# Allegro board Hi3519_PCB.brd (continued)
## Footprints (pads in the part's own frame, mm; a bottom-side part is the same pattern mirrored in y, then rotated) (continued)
CAPC2-138-335
  rect 2.032x2.032 hole 1.016: 1(0,0)
  round 2.032 hole 1.016: 2(3.5,0)
CONN80-0_8MM-ERF8-DV
  round 1.524 hole 1.524 unplated: (-17.4,-1.5) (17.4,-1.5)
  rect 0.508x1.27 smd: 1(15.6,2.2) 2(15.6,-2.2) 3(14.8,2.2) 4(14.8,-2.2) 5(14,2.2) 6(14,-2.2) 7(13.2,2.2) 8(13.2,-2.2) 9(12.4,2.2) 10(12.4,-2.2) 11(11.6,2.2) 12(11.6,-2.2) 13(10.8,2.2) 14(10.8,-2.2) 15(10,2.2) 16(10,-2.2) 17(9.2,2.2) 18(9.2,-2.2) 19(8.4,2.2) 20(8.4,-2.2) 21(7.6,2.2) 22(7.6,-2.2) 23(6.8,2.2) 24(6.8,-2.2) 25(6,2.2) 26(6,-2.2) 27(5.2,2.2) 28(5.2,-2.2) 29(4.4,2.2) 30(4.4,-2.2) 31(3.6,2.2) 32(3.6,-2.2) 33(2.8,2.2) 34(2.8,-2.2) 35(2,2.2) 36(2,-2.2) 37(1.2,2.2) 38(1.2,-2.2) 39(0.4,2.2) 40(0.4,-2.2) 41(-0.4,2.2) 42(-0.4,-2.2) 43(-1.2,2.2) 44(-1.2,-2.2) 45(-2,2.2) 46(-2,-2.2) 47(-2.8,2.2) 48(-2.8,-2.2) 49(-3.6,2.2) 50(-3.6,-2.2) 51(-4.4,2.2) 52(-4.4,-2.2) 53(-5.2,2.2) 54(-5.2,-2.2) 55(-6,2.2) 56(-6,-2.2) 57(-6.8,2.2) 58(-6.8,-2.2) 59(-7.6,2.2) 60(-7.6,-2.2) 61(-8.4,2.2) 62(-8.4,-2.2) 63(-9.2,2.2) 64(-9.2,-2.2) 65(-10,2.2) 66(-10,-2.2) 67(-10.8,2.2) 68(-10.8,-2.2) 69(-11.6,2.2) 70(-11.6,-2.2) 71(-12.4,2.2) 72(-12.4,-2.2) 73(-13.2,2.2) 74(-13.2,-2.2) 75(-14,2.2) 76(-14,-2.2) 77(-14.8,2.2) 78(-14.8,-2.2) 79(-15.6,2.2) 80(-15.6,-2.2)
CONN80-0_8MM-ERM8-DV
  round 1.524 hole 1.524 unplated: (-17.4,1.5) (17.4,1.5)
  rect 0.508x1.27 smd: 1(15.6,-1.9) 2(15.6,1.9) 3(14.8,-1.9) 4(14.8,1.9) 5(14,-1.9) 6(14,1.9) 7(13.2,-1.9) 8(13.2,1.9) 9(12.4,-1.9) 10(12.4,1.9) 11(11.6,-1.9) 12(11.6,1.9) 13(10.8,-1.9) 14(10.8,1.9) 15(10,-1.9) 16(10,1.9) 17(9.2,-1.9) 18(9.2,1.9) 19(8.4,-1.9) 20(8.4,1.9) 21(7.6,-1.9) 22(7.6,1.9) 23(6.8,-1.9) 24(6.8,1.9) 25(6,-1.9) 26(6,1.9) 27(5.2,-1.9) 28(5.2,1.9) 29(4.4,-1.9) 30(4.4,1.9) 31(3.6,-1.9) 32(3.6,1.9) 33(2.8,-1.9) 34(2.8,1.9) 35(2,-1.9) 36(2,1.9) 37(1.2,-1.9) 38(1.2,1.9) 39(0.4,-1.9) 40(0.4,1.9) 41(-0.4,-1.9) 42(-0.4,1.9) 43(-1.2,-1.9) 44(-1.2,1.9) 45(-2,-1.9) 46(-2,1.9) 47(-2.8,-1.9) 48(-2.8,1.9) 49(-3.6,-1.9) 50(-3.6,1.9) 51(-4.4,-1.9) 52(-4.4,1.9) 53(-5.2,-1.9) 54(-5.2,1.9) 55(-6,-1.9) 56(-6,1.9) 57(-6.8,-1.9) 58(-6.8,1.9) 59(-7.6,-1.9) 60(-7.6,1.9) 61(-8.4,-1.9) 62(-8.4,1.9) 63(-9.2,-1.9) 64(-9.2,1.9) 65(-10,-1.9) 66(-10,1.9) 67(-10.8,-1.9) 68(-10.8,1.9) 69(-11.6,-1.9) 70(-11.6,1.9) 71(-12.4,-1.9) 72(-12.4,1.9) 73(-13.2,-1.9) 74(-13.2,1.9) 75(-14,-1.9) 76(-14,1.9) 77(-14.8,-1.9) 78(-14.8,1.9) 79(-15.6,-1.9) 80(-15.6,1.9)
DFN2510P10E_AZ1045
  oval 0.254x0.813 smd: 1(-1,-0.525) 5(1,-0.525) 6(1,0.525) 10(-1,0.525)
  oval 0.229x0.813 smd: 2(-0.5,-0.525) 4(0.5,-0.525) 7(0.5,0.525) 9(-0.5,0.525)
  oval 0.356x0.813 smd: 3(0,-0.525) 8(0,0.525)
HEAD0101-T-B
  round 1.778 hole 1.016: 1(0,0)
HSC0402
  rect 0.508x0.508 smd: 1(-0.406,0) 2(0.406,0)
HSC0402-TA
  rect 0.432x0.508 smd: 1(-0.368,0) 2(0.368,0)
HSL1008
  rect 0.94x1.905 smd: 1(-1.029,0) 2(1.029,0)
HSOD323A
  rect 1.118x0.508 smd: 1(1.372,0) 2(-1.372,0)
HSOD882
  rect 0.406x0.483 smd: 1(-0.325,0) 2(0.325,0)
HSR0402-TA
  rect 0.432x0.508 smd: 1(-0.368,0) 2(0.368,0)
HSX2-0302
  rect 1.016x1.778 smd: 1(-1.25,0) 2(1.25,0)
HSX4-0302
  rect 1.397x1.219 smd: 1(-1.1,-0.8) 2(1.1,-0.8) 3(1.1,0.8) 4(-1.1,0.8)
HSX4-0503
  rect 1.524x1.219 smd: 1(-1.27,-1.1) 2(1.27,-1.1) 3(1.27,1.1) 4(-1.27,1.1)
J6-W2_54MM-141R
  rect 1.524x1.905 hole 0.965: 1(-6.35,-2.54)
  oval 1.524x1.905 hole 0.965: 2(-6.35,2.54) 3(-3.81,-2.54) 4(-3.81,2.54) 5(-1.27,-2.54) 6(-1.27,2.54) 7(1.27,-2.54) 8(1.27,2.54) 9(3.81,-2.54) 10(3.81,2.54) 11(6.35,-2.54) 12(6.35,2.54)
MJ8-SRLFY
  round 3.429 hole 3.429 unplated: (-2.794,2.54) (9.906,2.54)
  round 1.27 hole 0.914: 1(0,0) 2(1.016,-1.778) 3(2.032,0) 4(3.048,-1.778) 5(4.064,0) 6(5.08,-1.778) 7(6.096,0) 8(7.112,-1.778) 13(-3.302,-6.604) 14(-1.016,-6.604) 15(8.128,-6.604) 16(10.414,-6.604)
  round 2.159 hole 1.651: 11(-4.508,-0.889) 12(11.62,-0.889)
MLF6-065-0202L
  rect 0.305x0.457 smd: 1(-0.65,-0.925) 2(0,-0.925) 3(0.65,-0.925) 4(0.65,0.925) 5(0,0.925) 6(-0.65,0.925)
  rect 1.524x0.762 smd: 7(0,0)
MLF8M-050-0202L
  rect 0.254x0.559 smd: 1(-0.75,-0.623)
  rect 0.254x0.508 smd: 2(-0.25,-0.648) 3(0.25,-0.648) 4(0.75,-0.648) 5(0.75,0.648) 6(0.25,0.648) 7(-0.25,0.648) 8(-0.75,0.648)
MLF48A-040-0606L
  rect 0.203x0.61 smd: 1(-2.2,-2.879) 2(-1.8,-2.879) 3(-1.4,-2.879) 4(-1,-2.879) 5(-0.6,-2.879) 6(-0.2,-2.879) 7(0.2,-2.879) 8(0.6,-2.879) 9(1,-2.879) 10(1.4,-2.879) 11(1.8,-2.879) 12(2.2,-2.879) 25(2.2,2.879) 26(1.8,2.879) 27(1.4,2.879) 28(1,2.879) 29(0.6,2.879) 30(0.2,2.879) 31(-0.2,2.879) 32(-0.6,2.879) 33(-1,2.879) 34(-1.4,2.879) 35(-1.8,2.879) 36(-2.2,2.879)
  rect 0.61x0.203 smd: 13(2.879,-2.2) 14(2.879,-1.8) 15(2.879,-1.4) 16(2.879,-1) 17(2.879,-0.6) 18(2.879,-0.2) 19(2.879,0.2) 20(2.879,0.6) 21(2.879,1) 22(2.879,1.4) 23(2.879,1.8) 24(2.879,2.2) 37(-2.879,2.2) 38(-2.879,1.8) 39(-2.879,1.4) 40(-2.879,1) 41(-2.879,0.6) 42(-2.879,0.2) 43(-2.879,-0.2) 44(-2.879,-0.6) 45(-2.879,-1) 46(-2.879,-1.4) 47(-2.879,-1.8) 48(-2.879,-2.2)
  rect 4.445x4.445 smd: 49(0,0)
MLF56-050-1105
  rect 0.254x0.61 smd: 1(-4.75,-2.399) 2(-4.25,-2.399) 3(-3.75,-2.399) 4(-3.25,-2.399) 5(-2.75,-2.399) 6(-2.25,-2.399) 7(-1.75,-2.399) 8(-1.25,-2.399) 9(-0.75,-2.399) 10(-0.25,-2.399) 11(0.25,-2.399) 12(0.75,-2.399) 13(1.25,-2.399) 14(1.75,-2.399) 15(2.25,-2.399) 16(2.75,-2.399) 17(3.25,-2.399) 18(3.75,-2.399) 19(4.25,-2.399) 20(4.75,-2.399) 29(4.75,2.399) 30(4.25,2.399) 31(3.75,2.399) 32(3.25,2.399) 33(2.75,2.399) 34(2.25,2.399) 35(1.75,2.399) 36(1.25,2.399) 37(0.75,2.399) 38(0.25,2.399) 39(-0.25,2.399) 40(-0.75,2.399) 41(-1.25,2.399) 42(-1.75,2.399) 43(-2.25,2.399) 44(-2.75,2.399) 45(-3.25,2.399) 46(-3.75,2.399) 47(-4.25,2.399) 48(-4.75,2.399)
  rect 0.61x0.254 smd: 21(5.399,-1.75) 22(5.399,-1.25) 23(5.399,-0.75) 24(5.399,-0.25) 25(5.399,0.25) 26(5.399,0.75) 27(5.399,1.25) 28(5.399,1.75) 49(-5.399,1.75) 50(-5.399,1.25) 51(-5.399,0.75) 52(-5.399,0.25) 53(-5.399,-0.25) 54(-5.399,-0.75) 55(-5.399,-1.25) 56(-5.399,-1.75)
  rect 8.509x2.489 smd: 57(0,0)
MOLEX_47151
  round 1.219 hole 1.219 unplated: (-2.5,2.096) (2.5,2.096)
  oval 0.254x2.667 smd: 1(4.5,4.508) 2(4,4.508) 3(3.5,4.508) 4(3,4.508) 5(2.5,4.508) 6(2,4.508) 7(1.5,4.508) 8(1,4.508) 9(0.5,4.508) 10(0,4.508) 11(-0.5,4.508) 12(-1,4.508) 13(-1.5,4.508) 14(-2,4.508) 15(-2.5,4.508) 16(-3,4.508) 17(-3.5,4.508) 18(-4,4.508) 19(-4.5,4.508)
  oval 1.524x3.302 hole 0.711x2.718: 20(-7.25,3.746) 21(7.25,3.746)
  oval 1.524x2.718 hole 0.711x1.702: 22(-7.25,-2.214) 23(7.25,-2.214)
MSOP8A-26-118
  rect 0.356x1.524 smd: 1(-0.975,-2.2) 2(-0.325,-2.2) 3(0.325,-2.2) 4(0.975,-2.2) 5(0.975,2.2) 6(0.325,2.2) 7(-0.325,2.2) 8(-0.975,2.2)
MTH_C6MMD3P2MM
  round 6.096 hole 3.2: 1(0,0)
  round 0.61 hole 0.305: 2(2.5,0) 3(1.768,1.768) 4(0,2.5) 5(-1.768,1.768) 6(-2.5,0) 7(-1.768,-1.768) 8(0,-2.5) 9(1.768,-1.768)
PHONEJ6
  round 1.143 hole 1.143 unplated: (-2.54,0) (3.454,0)
  rect 1.27x2.032 smd: 1(3.454,3.556) 2(3.454,-3.556) 3(0.305,3.556) 4(0.305,-3.556) 5(-3.048,3.556) 6(-3.048,-3.556)
PWC0103-M-N
  rect 1.829x3.81 hole 0.813x2.794: 1(0,0)
  oval 1.829x4.064 hole 0.813x3.048: 2(-6,0)
  oval 3.556x1.829 hole 2.54x0.813: 3(-2.9,4.9)
QFN16-050-0303LH
  oval 0.254x0.889 smd: 1(-0.75,-1.5) 2(-0.25,-1.5) 3(0.25,-1.5) 4(0.75,-1.5) 9(0.75,1.5) 10(0.25,1.5) 11(-0.25,1.5) 12(-0.75,1.5)
  oval 0.889x0.254 smd: 5(1.5,-0.75) 6(1.5,-0.25) 7(1.5,0.25) 8(1.5,0.75) 13(-1.5,0.75) 14(-1.5,0.25) 15(-1.5,-0.25) 16(-1.5,-0.75)
  rect 1.651x1.651 smd: 17(0,0)
QFN-72
  oval 0.254x1.016 smd: 1(-4.25,-5) 2(-3.75,-5) 3(-3.25,-5) 4(-2.75,-5) 5(-2.25,-5) 6(-1.75,-5) 7(-1.25,-5) 8(-0.75,-5) 9(-0.25,-5) 10(0.25,-5) 11(0.75,-5) 12(1.25,-5) 13(1.75,-5) 14(2.25,-5) 15(2.75,-5) 16(3.25,-5) 17(3.75,-5) 18(4.25,-5) 37(4.25,5) 38(3.75,5) 39(3.25,5) 40(2.75,5) 41(2.25,5) 42(1.75,5) 43(1.25,5) 44(0.75,5) 45(0.25,5) 46(-0.25,5) 47(-0.75,5) 48(-1.25,5) 49(-1.75,5) 50(-2.25,5) 51(-2.75,5) 52(-3.25,5) 53(-3.75,5) 54(-4.25,5)
  oval 1.016x0.254 smd: 19(5,-4.25) 20(5,-3.75) 21(5,-3.25) 22(5,-2.75) 23(5,-2.25) 24(5,-1.75) 25(5,-1.25) 26(5,-0.75) 27(5,-0.25) 28(5,0.25) 29(5,0.75) 30(5,1.25) 31(5,1.75) 32(5,2.25) 33(5,2.75) 34(5,3.25) 35(5,3.75) 36(5,4.25) 55(-5,4.25) 56(-5,3.75) 57(-5,3.25) 58(-5,2.75) 59(-5,2.25) 60(-5,1.75) 61(-5,1.25) 62(-5,0.75) 63(-5,0.25) 64(-5,-0.25) 65(-5,-0.75) 66(-5,-1.25) 67(-5,-1.75) 68(-5,-2.25) 69(-5,-2.75) 70(-5,-3.25) 71(-5,-3.75) 72(-5,-4.25)
  rect 4.877x4.877 smd: 73(0,0)
SBAT2-13A
  rect 1.524x4.572 smd: 1(-1.913,-8.976)
  rect 1.524x4.191 smd: 2(1.913,-9.167)
SC0402
  rect 0.508x0.508 smd: 1(-0.406,0) 2(0.406,0)
SC0402-BGA
  custom 0.119x0.119 smd: 1(-0.47,0) 2(0.47,0)
SC0603
  rect 0.762x0.813 smd: 1(-0.699,0) 2(0.699,0)
SC0805
  rect 0.991x1.27 smd: 1(-0.813,0) 2(0.813,0)
SC1206
  rect 1.295x1.651 smd: 1(-1.346,0) 2(1.346,0)
SC1206C
  rect 1.295x1.651 smd: 1(-1.346,0) 2(1.346,0)
SC1210
  rect 1.295x2.413 smd: 1(-1.346,0) 2(1.346,0)
SC1210B
  rect 1.295x2.413 smd: 1(-1.346,0) 2(1.346,0)
SCAPC2-280-327
  rect 4.115x1.905 smd: 1(-3.55,0) 2(3.55,0)
SD0805-LED
  rect 1.27x1.397 smd: 1(-1.016,0) 2(1.016,0)
SD1714A
  rect 2.286x2.286 smd: 1(-2.286,0) 2(2.286,0)
SD1714D
  rect 2.286x2.286 smd: 1(-2.286,0) 2(2.286,0)
SD2723
  rect 2.794x3.81 smd: 1(-3.556,0) 2(3.556,0)
SED90-F-A
  rect 0.203x0.711 smd: 1(-8.8,-1.54) 2(-8.8,1.54) 3(-8.4,-1.54) 4(-8.4,1.54) 5(-8,-1.54) 6(-8,1.54) 7(-7.6,-1.54) 8(-7.6,1.54) 9(-7.2,-1.54) 10(-7.2,1.54) 11(-6.8,-1.54) 12(-6.8,1.54) 13(-6.4,-1.54) 14(-6.4,1.54) 15(-6,-1.54) 16(-6,1.54) 17(-5.6,-1.54) 18(-5.6,1.54) 19(-5.2,-1.54) 20(-5.2,1.54) 21(-4.8,-1.54) 22(-4.8,1.54) 23(-4.4,-1.54) 24(-4.4,1.54) 25(-4,-1.54) 26(-4,1.54) 27(-3.6,-1.54) 28(-3.6,1.54) 29(-3.2,-1.54) 30(-3.2,1.54) 31(-2.8,-1.54) 32(-2.8,1.54) 33(-2.4,-1.54) 34(-2.4,1.54) 35(-2,-1.54) 36(-2,1.54) 37(-1.6,-1.54) 38(-1.6,1.54) 39(-1.2,-1.54) 40(-1.2,1.54) 41(-0.8,-1.54) 42(-0.8,1.54) 43(-0.4,-1.54) 44(-0.4,1.54) 45(0,-1.54) 46(0,1.54) 47(0.4,-1.54) 48(0.4,1.54) 49(0.8,-1.54) 50(0.8,1.54) 51(1.2,-1.54) 52(1.2,1.54) 53(1.6,-1.54) 54(1.6,1.54) 55(2,-1.54) 56(2,1.54) 57(2.4,-1.54) 58(2.4,1.54) 59(2.8,-1.54) 60(2.8,1.54) 61(3.2,-1.54) 62(3.2,1.54) 63(3.6,-1.54) 64(3.6,1.54) 65(4,-1.54) 66(4,1.54) 67(4.4,-1.54) 68(4.4,1.54) 69(4.8,-1.54) 70(4.8,1.54) 71(5.2,-1.54) 72(5.2,1.54) 73(5.6,-1.54) 74(5.6,1.54) 75(6,-1.54) 76(6,1.54) 77(6.4,-1.54) 78(6.4,1.54) 79(6.8,-1.54) 80(6.8,1.54) 81(7.2,-1.54) 82(7.2,1.54) 83(7.6,-1.54) 84(7.6,1.54) 85(8,-1.54) 86(8,1.54) 87(8.4,-1.54) 88(8.4,1.54) 89(8.8,-1.54) 90(8.8,1.54)
SF6127
  rect 2.286x3.175 smd: 1(-2.54,0) 2(2.54,0)
SGM8903
  rect 0.356x1.524 smd: 1(-1.95,-2.921) 2(-1.3,-2.921) 3(-0.65,-2.921) 4(0,-2.921) 5(0.65,-2.921) 6(1.3,-2.921) 7(1.95,-2.921) 8(1.95,2.921) 9(1.3,2.921) 10(0.65,2.921) 11(0,2.921) 12(-0.65,2.921) 13(-1.3,2.921) 14(-1.95,2.921)
SIP-2P
  round 1.524 hole 1.143: 1(-1.27,0) 2(1.27,0)
SIP-2P-20
  oval 0.762x1.143 hole 0.508: 1(0,0) 2(1.25,0)
SL0402
  rect 0.483x0.508 smd: 1(-0.394,0) 2(0.394,0)
SL0603
  rect 0.711x0.813 smd: 1(-0.74,0) 2(0.74,0)
SL0805
  rect 0.94x1.27 smd: 1(-0.851,0) 2(0.851,0)
SL0805B
  rect 0.94x1.27 smd: 1(-0.851,0) 2(0.851,0)
SL2828
  rect 7.366x2.667 smd: 1(0,-2.325) 2(0,2.325)
SOP8-50-150
  rect 0.635x1.778 smd: 1(-1.905,-2.667) 2(-0.635,-2.667) 3(0.635,-2.667) 4(1.905,-2.667) 5(1.905,2.667) 6(0.635,2.667) 7(-0.635,2.667) 8(-1.905,2.667)
SOP16-50-300A
  rect 0.635x1.981 smd: 1(-4.445,-4.813) 2(-3.175,-4.813) 3(-1.905,-4.813) 4(-0.635,-4.813) 5(0.635,-4.813) 6(1.905,-4.813) 7(3.175,-4.813) 8(4.445,-4.813) 9(4.445,4.813) 10(3.175,4.813) 11(1.905,4.813) 12(0.635,4.813) 13(-0.635,4.813) 14(-1.905,4.813) 15(-3.175,4.813) 16(-4.445,4.813)
SOP48-20-720A
  rect 0.254x1.651 smd: 1(-5.75,-9.703) 2(-5.25,-9.703) 3(-4.75,-9.703) 4(-4.25,-9.703) 5(-3.75,-9.703) 6(-3.25,-9.703) 7(-2.75,-9.703) 8(-2.25,-9.703) 9(-1.75,-9.703) 10(-1.25,-9.703) 11(-0.75,-9.703) 12(-0.25,-9.703) 13(0.25,-9.703) 14(0.75,-9.703) 15(1.25,-9.703) 16(1.75,-9.703) 17(2.25,-9.703) 18(2.75,-9.703) 19(3.25,-9.703) 20(3.75,-9.703) 21(4.25,-9.703) 22(4.75,-9.703) 23(5.25,-9.703) 24(5.75,-9.703) 25(5.75,9.703) 26(5.25,9.703) 27(4.75,9.703) 28(4.25,9.703) 29(3.75,9.703) 30(3.25,9.703) 31(2.75,9.703) 32(2.25,9.703) 33(1.75,9.703) 34(1.25,9.703) 35(0.75,9.703) 36(0.25,9.703) 37(-0.25,9.703) 38(-0.75,9.703) 39(-1.25,9.703) 40(-1.75,9.703) 41(-2.25,9.703) 42(-2.75,9.703) 43(-3.25,9.703) 44(-3.75,9.703) 45(-4.25,9.703) 46(-4.75,9.703) 47(-5.25,9.703) 48(-5.75,9.703)
SOT23
  rect 1.016x1.27 smd: 1(-1.016,-1.143) 2(1.016,-1.143) 3(0,1.143)
SOT23-5B
  rect 0.508x1.422 smd: 1(-0.953,-1.397) 2(0,-1.397) 3(0.953,-1.397) 4(0.953,1.397) 5(-0.953,1.397)
SOT23-6B
  rect 0.635x1.397 smd: 1(-0.95,-1.225) 2(0,-1.225) 3(0.95,-1.225) 4(0.95,1.225) 5(0,1.225) 6(-0.95,1.225)
SOT23-6L
  rect 0.635x1.27 smd: 1(-0.95,-1.2) 2(0,-1.2) 3(0.95,-1.2) 4(0.95,1.2) 5(0,1.2) 6(-0.95,1.2)
SPL0303A
  rect 1.575x3.048 smd: 1(-1.201,0) 2(1.201,0)
SPL0404L
  rect 1.448x3.81 smd: 1(-1.775,0) 2(1.775,0)
SR0402
  rect 0.508x0.508 smd: 1(-0.406,0) 2(0.406,0)
SR0603
  rect 0.711x0.813 smd: 1(-0.737,0) 2(0.737,0)
SR0805
  rect 0.838x1.143 smd: 1(-0.927,0) 2(0.927,0)
SRLY8-87-283
  rect 0.889x2.794 smd: 1(-3.8,-3.378) 2(-0.6,-3.378) 3(1.6,-3.378) 4(3.8,-3.378) 5(3.8,3.378) 6(1.6,3.378) 7(-0.6,3.378) 8(-3.8,3.378)
STFM24-40-280
  rect 0.508x2.184 smd: 1(-5.5,-4.56) 2(-4.5,-4.56) 3(-3.5,-4.56) 4(-2.5,-4.56) 5(-1.5,-4.56) 6(-0.5,-4.56) 7(0.5,-4.56) 8(1.5,-4.56) 9(2.5,-4.56) 10(3.5,-4.56) 11(4.5,-4.56) 12(5.5,-4.56) 13(5.5,4.56) 14(4.5,4.56) 15(3.5,4.56) 16(2.5,4.56) 17(1.5,4.56) 18(0.5,4.56) 19(-0.5,4.56) 20(-1.5,4.56) 21(-2.5,4.56) 22(-3.5,4.56) 23(-4.5,4.56) 24(-5.5,4.56)
SW4_6M6X5M4
  rect 0.61x1.981 smd: 1(-1.875,-3.6) 2(-0.625,-3.6) 3(0.625,-3.6) 4(1.875,-3.6) 5(1.875,3.6) 6(0.625,3.6) 7(-0.625,3.6) 8(-1.875,3.6)
TF_CARD-MISOSD
  round 1.016 hole 1.016 unplated: (-4.95,-3) (3.05,-3)
  rect 0.711x1.651 smd: 1(2.25,7.5) 2(1.15,7.5) 3(0.05,7.5) 4(-1.05,7.5) 5(-2.15,7.5) 6(-3.25,7.5) 7(-4.35,7.5) 8(-5.45,7.5) 12(-6.55,7.5)
  rect 1.27x2.286 smd: 9(-7.75,-2.6) 13(7.75,-2.6)
  rect 1.219x1.397 smd: 10(-7.75,7)
  rect 1.651x1.397 smd: 11(6.85,7)
TSOT23-8
  rect 0.356x1.27 smd: 1(-0.975,-1.275) 2(-0.325,-1.275) 3(0.325,-1.275) 4(0.975,-1.275) 5(0.975,1.275) 6(0.325,1.275) 7(-0.325,1.275) 8(-0.975,1.275)
unnamed#2
  round 0.61 hole 0.61 unplated: (-2.2,1.1) (-1.1,1.1) (0,1.1) (1.1,1.1) (2.2,1.1)
unnamed#3
  round 1.016 smd: 1(0,0)
unnamed#4
  round 0.61 hole 0.61 unplated: (-2.2,1.1) (-2.2,-1.1) (-1.1,1.1) (-1.1,-1.1) (0,1.1) (0,-1.1) (1.1,1.1) (1.1,-1.1) (2.2,1.1) (2.2,-1.1)
USB4-200-1907
  oval 1.27x1.778 hole 0.914: 1(0,0) 2(2,0) 3(4,0) 4(6,0)
  round 2.032 hole 1.321: 5(-0.73,2.72) 6(6.27,2.72) 7(-0.73,-2.72) 8(6.27,-2.72)
VAF2
  rect 1.524x3.81 hole 1.016x3.048: 1(0,4.496)
  rect 3.048x2.032 hole 2.54x1.524: 2(0,0)
WBC0104-49T
  oval 0.762x1.143 hole 0.508: 1(0,0) 2(1.25,0) 3(2.5,0) 4(3.75,0)
WBC0108-49T
  oval 0.762x1.143 hole 0.508: 1(0,0) 2(1.25,0) 3(2.5,0) 4(3.75,0) 5(5,0) 6(6.25,0) 7(7.5,0) 8(8.75,0)
WSON8-MX25L12835ZN
  oval 0.635x1.524 smd: 1(-1.905,-3.8) 2(-0.635,-3.8) 3(0.635,-3.8) 4(1.905,-3.8) 5(1.905,3.8) 6(0.635,3.8) 7(-0.635,3.8) 8(-1.905,3.8)
  rect 4.648x4.75 smd: 9(0,0)

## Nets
0.9V_VDD: C33.1 C188.1 C206.1 C261.1 L8.1 LB7.2 R242.1 U3.K15 U3.M11 U3.M12 U3.N11 U3.N12 U3.P11 U3.P12 U3.R11 U3.R12
0.9V_VDD_CPU: C18.1 C31.1 C41.1 C42.1 C204.1 C268.1 L6.1 R240.1 U3.H13 U3.H14 U3.H15 U3.J14 U3.J15
0.9V_VDD_DDR: C30.1 C184.1 C185.1 C202.1 L5.1 R241.2 U3.H8 U3.H10 U3.H11 U3.J8
0.9V_VDD_MEDIA: C19.1 C20.1 C21.1 C22.1 C29.1 C43.1 C176.1 C201.1 C269.1 L4.2 R186.1 U3.N15 U3.P8 U3.P15 U3.R8 U3.R9 U3.R13 U3.R14 U3.R15 U18.5
1.2V_SII9022: C69.1 C76.1 C106.1 C224.1 C241.1 C243.1 LB15.1 LB17.1 U21.5 U21.6
1.8V: C32.1 C150.1 C177.1 C178.1 C205.1 L7.1 R14.2 R43.2 R51.2 R135.2 U3.M18 U3.V5 U3.V6 U3.V9 U3.V10
1V2A_SII9022A: C67.1 C68.1 C240.1 LB15.2 U22.60 U22.66
1V2D_SII9022A: C70.1 C74.1 C75.1 C78.1 C245.1 LB17.2 U22.5 U22.12 U22.26 U22.42 U22.47 U22.53
3V3: C10.1 C24.1 C27.1 C35.1 C36.1 C37.1 C38.1 C39.1 C40.1 C44.1 C49.1 C50.1 C51.1 C52.1 C53.1 C55.1 C58.1 C59.1 C77.1 C81.1 C82.1 C87.2 C88.1 C91.1 C105.1 C128.1 C133.1 C149.1 C151.1 C152.1 C175.1 C179.1 C180.1 C187.1 C189.1 C198.1 C200.1 C203.1 C207.1 C223.1 C227.1 C229.1 C230.1 C232.1 C235.1 C236.1 C244.1 C246.1 C262.1 C265.1 C266.1 D19.2 J18.14 J18.16 J18.18 J18.20 J21.1 J21.2 J25.1 L2.2 L12.2(TP-2) LB1.1 LB2.1 LB6.1 LB8.2 LB9.1 LB10.2 LB11.1 LB16.1 LB100.2 Q1.2 Q2.2 R5.1 R52.2 R53.2 R60.1 R61.1 R62.1 R63.1 R64.1 R65.1 R66.1 R67.1 R82.1 R83.1 R84.1 R85.1 R86.1 R87.2 R101.1 R102.2 R104.1 R105.1 R128.2 R136.2 R138.2 R139.2 R140.2 R142.2 R144.1 R145.1 R146.1 R147.1 R148.1 R149.2 R158.1 R159.1 R166.1 R218.1 R250.1 U2.15 U2.21 U3.E18 U3.E19 U3.J18 U3.N4 U3.P5 U3.R5 U3.T5 U3.T18 U3.V15 U4.8 U7.12 U7.37 U9.7 U10.4(TP-4) U10.10(TP-10) U10.18(TP-18) U10.27(TP-27) U10.38(TP-38) U10.50(TP-50) U10.56(TP-56) U13.5 U16.2 U18.2 U20.10 U20.15 U21.1 U21.3 U26.7 U27.7
3V3_C: C93.1 C100.1 C135.1 D15.1 J19.14 J19.16 J19.18 J19.20 R69.1 R77.1 U6.8
5V0: C80.1 C89.1 C92.1 C109.1 C129.1 C132.1 C196.1 C267.1 D20.2 J18.27 J18.29 J28.18 L1.2 L10.1 R246.2 U17.5
5V0_C: C94.1 C134.1 C142.1 J19.27 J19.29 L11.1 L88.1(TP-1) U1.6
5V_AUDIO: C9.1 C136.1 C182.1 C183.1 L11.2 U8.2 U8.3
5V_C_AUDIO: C5.1 C99.1 L88.2(TP-2) R233.2 U5.9
5V_USB2.0: C141.1 C208.1 J14.1 R234.1 U1.1
12V0: C110.1 C111.1 C114.1 C127.1 C130.1 C209.1 C217.1 C222.1 D1.2 F1.2 R74.1 R75.1 U23.2 U24.2
AGND: C5.2 C7.1 C9.2 C25.2 C26.2 C93.2 C94.2 C95.2 C96.2 C97.2 C98.2 C99.2 C100.2 C134.2 C135.2 C136.2 C137.2 C138.2 C140.1 C141.2 C142.2 C143.2 C144.2 C182.2 C183.2 C197.2 C208.2 C210.2 C211.2 C214.2 C215.2 C251.2 C252.2 C253.2 C254.2 C255.2 C256.2 C257.2 C258.2 C259.2 C260.2 D2.2 D3.2 D4.2 D5.2 D6.2 D7.2 D8.2 D9.2 D10.2 D11.2 D12.2 D13.2 D14.1 J10.1 J11.1 J14.4 J14.5 J14.6 J14.7 J14.8 J15.2 J19.7 J19.12 J19.15 J19.21 J19.22 J19.25 J19.31 J19.47 J19.50 J19.51 J19.55 J19.56 J19.59 J19.63 J19.64 J19.67 J19.68 J19.71 J19.72 J19.75 J19.76 J19.79 J19.80 J29.5 J29.6 J30.5 J30.6 M5.1 M5.2 M5.3 M5.4 M5.5 M5.6 M5.7 M5.8 M5.9 M6.1 M6.2 M6.3 M6.4 M6.5 M6.6 M6.7 M6.8 M6.9 Q6.2 R15.1 R58.2 R59.2 R106.1 R107.1 R112.2 R123.1 R127.1 R152.2 R169.1 R171.2 R234.2 R236.1 R239.1 U1.5 U1.7 U5.1 U5.4 U5.10 U5.14 U6.5 U8.7
AVDD33_AC: C23.2 LB9.2 U3.V18
AVDD33_PLL: C46.1 LB8.1 U3.M5
AVDD33_USB2: C777.1 LB100.1 U3.G18
AVDD33_VDAC: C48.1 LB10.1 U3.V17
AVDD_1.05V: C62.1 C63.1 C64.1 C238.1 LB5.2 U2.3 U2.9 U2.40
AVDD_3V3_PHY: C56.1 C233.1 LB1.2 U2.6 U2.41
AVDD_DDRPLL: C800.1 C801.1 LB6.2 U3.E11 U3.J5
AVDD_PLL: C45.1 LB7.1 U3.N8
DDRIO_1.5V/1.35V: C28.1 C34.1 C101.1 C145.1 C146.1 C147.1 C148.1 C154.1 C155.1 C157.1 C158.1 C160.1 C162.1 C163.1 C164.1 C165.1 C166.1 C167.1 C168.1 C169.1 C170.1 C171.1 C172.1 C173.1 C174.1 C186.1 C199.1 C225.1 C226.1 C270.1 C271.1 L3.2 R31.2 R174.2 R176.2 R179.2 R181.2 U3.E5 U3.E6 U3.E7 U3.E12 U3.E13 U3.F5 U3.G5 U3.H5 U9.4 U14.A1 U14.A8 U14.B2 U14.C1 U14.C9 U14.D2 U14.D9 U14.E9 U14.F1 U14.G7 U14.H2 U14.H9 U14.K2 U14.K8 U14.N1 U14.N9 U14.R1 U14.R9 U15.A1 U15.A8 U15.B2 U15.C1 U15.C9 U15.D2 U15.D9 U15.E9 U15.F1 U15.G7 U15.H2 U15.H9 U15.K2 U15.K8 U15.N1 U15.N9 U15.R1 U15.R9
DVDD_1.05V: C60.1 C61.1 C237.1 LB4.2 U2.28 U2.36
GND: C1.2 C2.2 C3.2 C4.2 C6.2 C10.2 C13.2 C14.2 C15.2 C16.2 C17.2 C18.2 C19.2 C20.2 C21.2 C22.2 C23.1 C24.2 C27.2 C28.2 C29.2 C30.2 C31.2 C32.2 C33.2 C34.2 C35.2 C36.2 C37.2 C38.2 C39.2 C40.2 C41.2 C42.2 C43.2 C44.2 C45.2 C46.2 C47.2 C48.2 C49.2 C50.2 C51.2 C52.2 C53.2 C54.2 C55.2 C56.2 C57.2 C58.2 C59.2 C60.2 C61.2 C62.2 C63.2 C64.2 C65.2 C66.2 C67.2 C68.2 C69.2 C70.2 C71.2 C72.2 C73.2 C74.2 C75.2 C76.2 C77.2 C78.2 C79.1 C80.2 C81.2 C82.2 C83.2 C84.2 C85.2 C86.2 C88.2 C89.2 C90.2 C91.2 C92.2 C101.2 C105.2 C106.2 C109.2 C110.2 C111.2 C112.2 C114.2 C115.2 C117.2 C118.2 C119.2 C120.2 C121.2 C122.2 C123.2 C124.1 C127.2 C128.2 C129.2 C130.2 C131.2 C132.2 C133.2 C145.2 C146.2 C147.2 C148.2 C149.2 C150.2 C151.2 C152.2 C153.2 C154.2 C155.2 C156.2 C157.2 C158.2 C159.2 C160.2 C161.2 C162.2 C163.2 C164.2 C165.2 C166.2 C167.2 C168.2 C169.2 C170.2 C171.2 C172.2 C173.2 C174.2 C175.2 C176.2 C177.2 C178.2 C184.2 C185.2 C186.2 C187.2 C188.2 C189.2 C190.1 C193.1 C196.2 C198.2 C199.2 C200.2 C201.2 C202.2 C203.2 C204.2 C205.2 C206.2 C207.2 C209.2 C212.1 C213.2 C216.2 C217.2 C218.2 C219.2 C220.2 C221.2 C222.2 C223.2 C224.2 C225.2 C226.2 C227.2 C228.2 C229.2 C230.2 C231.2 C232.2 C233.2 C234.2 C235.2 C236.2 C237.2 C238.2 C239.2 C240.2 C241.2 C242.2 C243.2 C244.2 C245.2 C246.2 C247.2 C248.2 C261.2 C262.2 C263.2 C264.2 C265.2 C266.2 C267.2 C268.2 C269.2 C270.2 C271.2 C777.2 C800.2 C801.2 D1.1 D17.2 J1.1 J1.7 J1.10 J1.13 J1.19 J1.22 J1.25 J1.28 J1.31 J1.34 J1.37 J1.40 J1.43 J1.46 J1.49 J1.52 J1.55 J1.61 J1.62 J1.67 J1.73 J1.74 J1.79 J1.85 J2.1 J3.1 J4.1 J5.1 J12.6 J12.9 J12.10 J12.11 J12.13 J13.6 J13.9 J13.10 J13.11 J13.13 J16.1 J16.3 J18.7 J18.12 J18.15 J18.21 J18.22 J18.25 J18.31 J18.47 J18.50 J18.51 J18.55 J18.56 J18.59 J18.63 J18.64 J18.67 J18.68 J18.71 J18.72 J18.75 J18.76 J18.79 J18.80 J20.11 J20.12 J20.13 J21.8 J25.4 J26.1 J28.2 J28.5 J28.8 J28.11 J28.17 J28.20 J28.21 J28.22 J28.23 J50.1 M1.1 M1.2 M1.3 M1.4 M1.5 M1.6 M1.7 M1.8 M1.9 M2.1 M2.2 M2.3 M2.4 M2.5 M2.6 M2.7 M2.8 M2.9 M3.1 M3.2 M3.3 M3.4 M3.5 M3.6 M3.7 M3.8 M3.9 M4.1 M4.2 M4.3 M4.4 M4.5 M4.6 M4.7 M4.8 M4.9 OSC1.2(TP-2) Q3.2 Q4.2 R11.2 R12.2 R13.2 R33.1 R34.1 R35.2 R38.2 R39.2 R40.2 R41.1 R42.1 R44.1 R45.1 R46.1 R47.1 R48.1 R49.1 R50.1 R55.2 R56.2 R68.1 R70.2 R71.2 R78.2 R80.2 R81.2 R89.1 R91.2 R92.2 R93.2 R94.2 R98.1 R103.1 R108.2 R109.2 R113.1 R114.1 R115.1 R129.1 R137.1 R141.2 R143.2 R151.2 R167.2 R168.2 R175.1 R177.1 R178.1 R180.1 R182.2 R187.1 R214.2 R232.2 R243.2 R244.2 R245.1 R252.2 R253.1 R558.1 U2.47 U2.49 U3.A1 U3.A2 U3.A6 U3.A13 U3.A22 U3.AB1 U3.AB14 U3.AB22 U3.B6 U3.B13 U3.B16 U3.C11 U3.C19 U3.D7 U3.D19 U3.E4 U3.E8 U3.E9 U3.E10 U3.E14 U3.E20 U3.F20 U3.G4 U3.G19 U3.G21 U3.G22 U3.H9 U3.H12 U3.H20 U3.J9 U3.J10 U3.J11 U3.J12 U3.J13 U3.K3 U3.K5 U3.K8 U3.K9 U3.K10 U3.K11 U3.K12 U3.K13 U3.K14 U3.K18 U3.K19 U3.K21 U3.K22 U3.L5 U3.L8 U3.L9 U3.L10 U3.L11 U3.L12 U3.L13 U3.L14 U3.L15 U3.M4 U3.M8 U3.M9 U3.M10 U3.M13 U3.M14 U3.M15 U3.M20 U3.N1 U3.N2 U3.N5 U3.N9 U3.N10 U3.N13 U3.N14 U3.N18 U3.P3 U3.P9 U3.P10 U3.P13 U3.P14 U3.P21 U3.R10 U3.U2 U3.U21 U3.V4 U3.V8 U3.V16 U3.W7 U3.W10 U3.W19 U3.W20 U3.Y7 U3.Y10 U3.Y20 U4.4 U4.9 U7.13 U7.36 U9.3 U9.5 U10.1(TP-1) U10.6(TP-6) U10.9(TP-9) U10.13(TP-13) U10.16(TP-16) U10.21(TP-21) U10.24(TP-24) U10.28(TP-28) U10.33(TP-33) U10.39(TP-39) U10.44(TP-44) U10.49(TP-49) U10.53(TP-53) U10.55(TP-55) U10.57(TP-57) U11.3 U11.8 U12.3 U12.8 U13.1 U13.3 U14.A9 U14.B1 U14.B3 U14.B9 U14.D1 U14.D8 U14.E1 U14.E2 U14.E8 U14.F9 U14.G1 U14.G8 U14.G9 U14.J2 U14.J8 U14.M1 U14.M9 U14.P1 U14.P9 U14.T1 U14.T9 U15.A9 U15.B1 U15.B3 U15.B9 U15.D1 U15.D8 U15.E1 U15.E2 U15.E8 U15.F9 U15.G1 U15.G8 U15.G9 U15.J2 U15.J8 U15.M1 U15.M9 U15.P1 U15.P9 U15.T1 U15.T9 U16.10 U17.2 U18.4 U18.6 U19.4 U20.11 U20.17 U21.2 U22.43 U22.57 U22.63 U22.73 U23.4 U24.4 U25.2 U26.5 U27.5 X1.2 X1.4
VDDREG_3.3V: C57.1 C234.1 LB2.2 U2.37 U2.44 U2.45
A+: J27.3 U20.16
A-: J27.2 U20.2
AC_IN0_N_C: C253.1 C260.1 D9.1 J22.1 R126.2 R223.1
AC_IN0L_C: C137.1 D6.1 J29.1 R117.1 R221.1
AC_IN0R_C: C138.1 D5.1 J29.3 R119.1 R222.1
AC_IN1_N: C195.1 J18.53
AC_IN1_N_C: C251.1 C258.1 D7.1 J19.53 J23.1 R122.2
AC_IN1_P: C194.1 J18.49
AC_IN1_P_C: C252.1 C257.1 D8.1 J19.49 J23.2 R121.1
AC_INO_P_C: C254.1 C259.1 D10.1 J22.2 R125.1 R220.1
AC_MICBIAS0: C190.2 R95.1 R208.1 R209.1 U3.W22
AC_MICBIAS0_DIF: J18.57 R95.2
AC_MICBIAS0_DIF_C: C98.1 C256.1 J19.57 R124.2
AC_MICBIAS0_L: J18.65 R208.2
AC_MICBIAS0_L_C: C97.1 J19.65 R116.2
AC_MICBIAS0_R: J18.61 R209.2
AC_MICBIAS0_R_C: C96.1 J19.61 R118.1
AC_MICBIAS1: C193.2 J18.69 U3.W21
AC_MICBIAS1_C: C95.1 C255.1 J19.69 R120.2
AC_MICIN0_L/DIFFIN0_P: C191.1 J18.73
AC_MICIN0_L/DIFFIN0_P_C: J19.73 R220.2 R221.2
AC_MICIN0_R/DIFFIN0_N: C192.1 J18.77
AC_MICIN0_R/DIFFIN0_N_C: J19.77 R222.2 R223.2
AC_OUTL: J18.70 U3.AA22
AC_OUTL/AC_OUTR: C139.1 R228.2 R229.2
AC_OUTL_C: J19.70 R225.2 R226.2
AC_OUTL_PAM8303D: R225.1 R228.1
AC_OUTL_SGM8903: C126.2 R107.2 R226.1
AC_OUTR: J18.74 U3.AA21
AC_OUTR_C: J19.74 R224.2 R227.2
AC_OUTR_PAM8303D: R224.1 R229.1
AC_OUTR_SGM8903: C125.1 R106.2 R227.1
AN0: R144.2 R1002.2 U2.17
AN1: R145.2 R1003.2 U2.18
B+: J27.4 U20.5
B-: J27.1 U20.3
CEC_A_SII9022A: R6.1 R219.2 U17.3 U22.71
DAMP+: J26.3 LB13.2 R167.1
DAMP-: J26.4 LB14.2 R168.1
DC_IRIS_PWM: R2.1 U3.Y14
DDR3_A0: U3.H4 U14.N3 U15.N3
DDR3_A1: U3.F3 U14.P7 U15.P7
DDR3_A2: U3.H2 U14.P3 U15.P3
DDR3_A3: U3.D2 U14.N2 U15.N2
DDR3_A4: U3.K4 U14.P8 U15.P8
DDR3_A5: U3.J4 U14.P2 U15.P2
DDR3_A6: U3.G2 U14.R8 U15.R8
DDR3_A7: U3.J3 U14.R2 U15.R2
DDR3_A8: U3.H1 U14.T8 U15.T8
DDR3_A9: U3.J2 U14.R3 U15.R3
DDR3_A10: U3.E3 U14.L7 U15.L7
DDR3_A11: U3.F1 U14.R7 U15.R7
DDR3_A12: U3.G3 U14.N7 U15.N7
DDR3_A13: U3.J1 U14.T3 U15.T3
DDR3_A14: U3.F2 U14.T7 U15.T7
DDR3_A15: U3.F4 U14.M7 U15.M7
DDR3_BA0: U3.C1 U14.M2 U15.M2
DDR3_BA1: U3.G1 U14.N8 U15.N8
DDR3_BA2: U3.E1 U14.M3 U15.M3
DDR3_CAS_N: U3.D1 U14.K3 U15.K3
DDR3_CKE: U3.C3 U14.K9 U15.K9
DDR3_CLK_N: R7.1 U3.B1 U14.K7 U15.K7
DDR3_CLK_P: R7.2 U3.B2 U14.J7 U15.J7
DDR3_CS_N: U3.E2 U14.L2 U15.L2
DDR3_DM0: U3.D10 U14.E7
DDR3_DM1: U3.C15 U14.D3
DDR3_DM2: U3.D5 U15.E7
DDR3_DM3: U3.C8 U15.D3
DDR3_DQ0: U3.D14 U14.E3
DDR3_DQ1: U3.D11 U14.F7
DDR3_DQ2: U3.D12 U14.F2
DDR3_DQ3: U3.B10 U14.F8
DDR3_DQ4: U3.D13 U14.H3
DDR3_DQ5: U3.A10 U14.H8
DDR3_DQ6: U3.A16 U14.G2
DDR3_DQ7: U3.C12 U14.H7
DDR3_DQ8: U3.C13 U14.D7
DDR3_DQ9: U3.C14 U14.C3
DDR3_DQ10: U3.D9 U14.C8
DDR3_DQ11: U3.D15 U14.C2
DDR3_DQ12: U3.B11 U14.A7
DDR3_DQ13: U3.B15 U14.A2
DDR3_DQ14: U3.A11 U14.B8
DDR3_DQ15: U3.A15 U14.A3
DDR3_DQ16: U3.D8 U15.E3
DDR3_DQ17: U3.D6 U15.F7
DDR3_DQ18: U3.A3 U15.F2
DDR3_DQ19: U3.B9 U15.F8
DDR3_DQ20: U3.C7 U15.H3
DDR3_DQ21: U3.A4 U15.H8
DDR3_DQ22: U3.B3 U15.G2
DDR3_DQ23: U3.C5 U15.H7
DDR3_DQ24: U3.C10 U15.D7
DDR3_DQ25: U3.C9 U15.C3
DDR3_DQ26: U3.A9 U15.C8
DDR3_DQ27: U3.B8 U15.C2
DDR3_DQ28: U3.C6 U15.A7
DDR3_DQ29: U3.B4 U15.A2
DDR3_DQ30: U3.A8 U15.B8
DDR3_DQ31: U3.C4 U15.A3
DDR3_DQS0_N: U3.A14 U14.G3
DDR3_DQS0_P: U3.B14 U14.F3
DDR3_DQS1_N: U3.A12 U14.B7
DDR3_DQS1_P: U3.B12 U14.C7
DDR3_DQS2_N: U3.A7 U15.G3
DDR3_DQS2_P: U3.B7 U15.F3
DDR3_DQS3_N: U3.A5 U15.B7
DDR3_DQS3_P: U3.B5 U15.C7
DDR3_ODT: U3.D3 U14.K1 U15.K1
DDR3_RAS_N: U3.D4 U14.J3 U15.J3
DDR3_RESET_N: U3.H3 U14.T2 U15.T2
DDR3_WE_N: U3.C2 U14.L3 U15.L3
DRIVE+: J26.2 LB12.2 R165.2
DRIVING+_G: C1.1 LB12.1 R32.2
EPHY_CLK: R216.1 U10.48(TP-48)
EPHY_CLK/VO_DATA8: R21.1 U10.2(TP-2)
EPHY_RSTN/SPI_NAND_SEL: C213.1 R87.1 R558.2 U2.29 U3.D16
FLASH_TRIG: J18.62 U3.W15
FLASH_TRIG_C: J19.62 R59.1 R185.1
FLASH_TRIG_COM: J17.9 J17.10 K1.3
FLASH_TRIG_NO: J17.7 J17.8 K1.4
HOT_PLUG_SII9022A: C79.2 J28.19 R37.2 R68.2 U17.4
I2C3_SCL: R53.1 U3.AB17 U22.1
I2C3_SDA: R52.1 U3.AB16 U22.2
IO3V3_SII9022A: C71.1 C72.1 C73.1 C242.1 LB16.2 R150.2 U22.3 U22.21 U22.46
IRCUT_CONTROL1: J1.76 U3.AB15
IRCUT_CONTROL2: J1.78 U3.AA17
IRIS_5V0: C6.1 C86.1 C117.1 C131.1 L10.2 Q5.3 R165.1 U19.8
JTAG_EN: R65.2 SW2.2 U3.K2
JTAG_RSTN: J21.3 U3.L2
JTAG_TCK: J21.6 U3.L1
JTAG_TDI: J21.4 U3.L4
JTAG_TDO: J21.7 U3.L3
JTAG_TMS: J21.5 U3.M3
LED0_ACTIVE/PHY_AD0: J20.15 R142.1 U2.34
LED1_LINK/PHY_AD1: R4.1 R143.1 U2.35
MDCK: R800.1 U2.30
MDIN0: T1.3 U2.2
MDIN1: T1.6 U2.5
MDIN2: T1.9 U2.8
MDIN3: T1.12 U2.11
MDIO: R102.1 U2.31 U3.D17
MDIP0: T1.2 U2.1
MDIP1: T1.5 U2.4
MDIP2: T1.8 U2.7
MDIP3: T1.11 U2.10
MIPI0_CKM: J1.21 U3.Y6
MIPI0_CKP: J1.23 U3.W6
MIPI0_D0M: J1.9 U3.AA7
MIPI0_D0P: J1.11 U3.AB7
MIPI0_D1M: J1.3 U3.AA6
MIPI0_D1P: J1.5 U3.AB6
MIPI0_D2M: J1.27 U3.W8
MIPI0_D2P: J1.29 U3.Y8
MIPI0_D3M: J1.15 U3.AA5
MIPI0_D3P: J1.17 U3.AB5
MIPI1_CKM: J1.47 U3.W9
MIPI1_CKP: J1.45 U3.Y9
MIPI1_D0M: J1.53 U3.AB10
MIPI1_D0P: J1.51 U3.AA10
MIPI1_D1M: J1.41 U3.AB9
MIPI1_D1P: J1.39 U3.AA9
MIPI1_D2M: J1.59 U3.AB11
MIPI1_D2P: J1.57 U3.AA11
MIPI1_D3M: J1.35 U3.AB8
MIPI1_D3P: J1.33 U3.AA8
MIPI2_CKM: J1.77 U3.W12
MIPI2_CKP: J1.75 U3.Y12
MIPI2_D0M: J1.83 U3.Y13
MIPI2_D0P: J1.81 U3.W13
MIPI2_D1M: J1.71 U3.AB12
MIPI2_D1P: J1.69 U3.AA12
MIPI2_D2M: J1.89 U3.AB13
MIPI2_D2P: J1.87 U3.AA13
MIPI2_D3M: J1.65 U3.Y11
MIPI2_D3P: J1.63 U3.W11
MP2143_FB: R186.2 R191.2 R194.2 R232.1
MUTE: J18.78 U3.AA14
MUTE_C: J19.78 R58.1 R169.2 U5.5 U8.6
MX0+: J20.1 T1.23
MX0-: J20.2 T1.22
MX1+: J20.3 T1.20
MX1-: J20.6 T1.19
MX2+: J20.4 T1.17
MX2-: J20.5 T1.16
MX3+: J20.7 T1.14
MX3-: J20.8 T1.13
NF_ALE: U3.V1 U7.17
NF_CLE: U3.V2 U7.16
NF_CSN/SFC_CSN0: R139.1 U3.R1 U4.1 U7.9 U16.7
NF_DQ0/SFC_HOLD_IO3: R138.1 R212.2 U3.R4 U7.29 U16.1
NF_DQ1/SFC_CLK: R801.1 U4.6 U7.30 U16.16
NF_DQ2: U3.T3 U7.31
NF_DQ3/SFC_SDO_IO0: U3.T2 U4.5 U7.32 U16.15
NF_DQ4: U3.U3 U7.41
NF_DQ5: U3.T4 U7.42
NF_DQ6: U3.U4 U7.43
NF_DQ7: U3.V3 U7.44
NF_RDY/SFC_WP_IO2: R137.2 R140.1 U3.U1 U4.3 U7.7 U16.9
NF_REN/SFC_SDI_IO1: U3.T1 U4.2 U7.8 U16.8
NF_WEN: U3.W1 U7.18
P_IRIS_CONTROL1: U3.AA19 U20.14
P_IRIS_CONTROL2: U3.AB18 U20.13
P_IRIS_CONTROL3: U3.AB19 U20.7
P_IRIS_CONTROL4: U3.AA18 U20.8
PER_RSTN: R36.1 U13.4
PHY_AD2: R141.1 R1005.2 U2.13
REG_OUT_1.05V: C54.1 C231.1 L9.2 LB4.1 LB5.1
RGMII_RX_CLK: R1004.1 U10.42(TP-42)
RGMII_RX_CLK/VO_DATA11: U3.C18 U10.8(TP-8)
RGMII_RX_DV/PHY_AD2: R1005.1 U10.31(TP-31)
RGMII_RX_DV/PHY_AD2/VO_DATA15: U3.A17 U10.15(TP-15)
RGMII_RXD0/SELRGV: R1000.1 U3.B17
RGMII_RXD1/TXDLY: R1001.1 U10.32(TP-32)
RGMII_RXD1/TXDLY/VO_DATA14: U3.A18 U10.14(TP-14)
RGMII_RXD2/AN0: R1002.1 U10.36(TP-36)
RGMII_RXD2/AN0/VO_DATA13: U3.B18 U10.12(TP-12)
RGMII_RXD3/AN1: R1003.1 U10.37(TP-37)
RGMII_RXD3/AN1/VO_DATA12: U3.A19 U10.11(TP-11)
RGMII_TX_CLK: U2.22 U10.52(TP-52)
RGMII_TX_CLK/VO_DE: R19.1 U10.54(TP-54)
RGMII_TX_EN: R90.1 U2.27
RGMII_TXD0: U2.23 U10.43(TP-43)
RGMII_TXD0/VO_DATA10: R8.1 U10.7(TP-7)
RGMII_TXD1: U2.24 U10.22(TP-22)
RGMII_TXD1/VO_VS: R20.1 U10.19(TP-19)
RGMII_TXD2: U2.25 U10.47(TP-47)
RGMII_TXD2/VO_DATA9: R25.1 U10.3(TP-3)
RGMII_TXD3: U2.26 U10.23(TP-23)
RGMII_TXD3/VO_HS: R88.1 U10.20(TP-20)
RS485_A_D+: D13.1 J17.3 J17.4 R18.1 R889.2
RS485_B_D-: D14.2 J17.1 J17.2 R18.2 R888.2
RXDLY: R147.2 U2.32
SAR_ADC0: J50.2 U3.W2
SDIO0_CARD_DETECT: J13.12 R159.2 U3.T21
SDIO0_CARD_POWER_EN: R56.1 R57.1 U3.N19
SDIO0_CCLK_OUT: J13.5 R26.2
SDIO0_CCMD: J13.3 R164.2 R784.2
SDIO0_CDATA0: J13.7 R162.2 R776.2
SDIO0_CDATA1: J13.8 R161.2 R778.2
SDIO0_CDATA2: J13.1 R160.2 R780.2
SDIO0_CDATA3: J13.2 R163.2 R782.2
SDIO0_VDD_3.3V: C84.1 C248.1 J13.4 Q2.3 R71.1
SDIO0_VOUT: R160.1 R161.1 R162.1 R163.1 R164.1 U3.P20
SDIO1_CARD_DETECT: J12.12 R158.2 U3.L20
SDIO1_CARD_POWER_EN: R54.1 R55.1 U3.K20
SDIO1_CCLK_OUT: J12.5 R27.2
SDIO1_CCMD: J12.3 R153.2 R786.2
SDIO1_CDATA0: J12.7 R155.2 R884.2
SDIO1_CDATA1: J12.8 R156.2 R882.2
SDIO1_CDATA2: J12.1 R157.2 R880.2
SDIO1_CDATA3: J12.2 R154.2 R788.2
SDIO1_VDD_3.3V: C83.1 C247.1 J12.4 Q1.3 R70.1
SDIO1_VOUT: R153.1 R154.1 R155.1 R156.1 R157.1 U3.M19
SELRGV: R148.2 R1000.2 U2.14
SENSOR_CLK: J1.12 R22.1
SENSOR_HS: J1.18 R23.1
SENSOR_RSTN: J1.14 U3.Y4
SENSOR_VS: J1.20 R24.1
SGM8903_OUTL: C215.1 D12.1 J30.1 R133.2
SGM8903_OUTR: C214.1 D11.1 J30.3 R134.1
SHUTTER_TRIG: J18.60 U3.W14
SHUTTER_TRIG_C: J17.5 J17.6 J19.60
SPI0_CSN: J1.2 R135.1 U3.AB4
SPI0_MISO: J1.4 U3.AB3
SPI0_MOSI/I2C0_SDA: J1.6 R51.1 U3.AB2
SPI0_SCLK/I2C0_SCL: J1.8 R43.1 R500.1
SVB_PWM_CPU: R200.1 U3.W16
SVB_PWM_DDR: R202.2 U3.Y17
SVB_PWM_MEDIA: R192.1 U3.Y16
SVB_PWM_VDD: R207.1 U3.Y15
SYS_RSTN_OUT: C212.2 R213.2 U3.P4 U13.2 U16.3
TEST_MODE: R93.1 U3.R2
TX0+_SII9022A: J28.7 U12.1 U12.10 U22.62
TX0-_SII9022A: J28.9 U12.2 U12.9 U22.61
TX1+_SII9022A: J28.4 U11.4 U11.7 U22.65
TX1-_SII9022A: J28.6 U11.5 U11.6 U22.64
TX2+_SII9022A: J28.1 U11.1 U11.10 U22.68
TX2-_SII9022A: J28.3 U11.2 U11.9 U22.67
TX_DSCL_SII9022A: J28.15 R183.1 U17.1 U22.49
TX_DSDA_SII9022A: J28.16 R184.1 U17.6 U22.48
TXC+_SII9022A: J28.10 U12.4 U12.7 U22.59
TXC-_SII9022A: J28.12 U12.5 U12.6 U22.58
TXDLY: R146.2 R1001.2 U2.16
UART0_RXD: J25.3 U3.Y19
UART0_TXD: J25.2 U3.Y18
UART1_RTSN: J18.58 U3.V20
UART1_RTSN_C: J19.58 R230.1 R231.1
UART1_RXD: J18.52 U3.U20
UART1_RXD_C: J19.52 U6.1
UART1_TXD: J18.54 U3.V19
UART1_TXD_C: J19.54 U6.4
USB2_DM: J18.17 U3.F22
USB2_DM_C: D4.1 J14.2 J19.17
USB2_DP: J18.19 U3.F21
USB2_DP_C: D3.1 J14.3 J19.19
USB2_OVRCUR: J18.11 U3.AA16
USB2_OVRCUR_C: J19.11 R69.2 U1.3
USB2_PWREN: J18.9 U3.F19
USB2_PWREN_C: J19.9 R152.1 U1.4
VDAC_CVBS: J18.66 R129.2 U3.AB20
VDAC_CVBS_C: D2.1 J15.1 J19.66
VO_CLK: R700.1 U22.22
VO_DATA0/BOOT_SEL0: R60.2 SW1.4 U3.E22 U22.13
VO_DATA1/BOOT_SEL1: R61.2 SW1.3 U3.E21 U22.11
VO_DATA2/BOOTROM_SEL: R67.2 SW2.4 U3.D22 U22.10
VO_DATA3/SFC_EMMC_BOOT_MODE: R63.2 SW1.1 U3.D21 U22.9
VO_DATA4/SFC_DEVICE_MODE: R62.2 SW1.2 U3.C22 U22.8
VO_DATA5: U3.C21 U22.7
VO_DATA6/UPDATE_FROM_SDIO0: R66.2 SW2.3 U3.D20 U22.6
VO_DATA7: U3.C20 U22.4
VO_DATA8: U10.46(TP-46) U22.23
VO_DATA9: U10.45(TP-45) U22.20
VO_DATA10: U10.41(TP-41) U22.19
VO_DATA11: U10.40(TP-40) U22.18
VO_DATA12: U10.35(TP-35) U22.17
VO_DATA13: U10.34(TP-34) U22.16
VO_DATA14: U10.30(TP-30) U22.15
VO_DATA15: U10.29(TP-29) U22.14
VO_DE: U10.51(TP-51) U22.33
VO_HS: U10.26(TP-26) U22.34
VO_RGMII_SWITCH: R64.2 SW2.1 U10.17(TP-17)
VO_VS: U10.25(TP-25) U22.35
$5N25: C115.1 R73.1 U23.7
$5N30: R73.2 R81.1 U23.1
$5N37: R74.2 U23.6
$5N45: C116.1 R248.2
$5N49: C116.2 L2.1 U23.3
$5N52: R248.1 U23.5
$5N55: R100.1 U23.8
$5N85: R99.1 U24.8
$5N86: R247.1 U24.5
$5N87: C113.2 L1.1 U24.3
$5N88: C113.1 R247.2
$5N91: R75.2 U24.6
$5N94: R72.2 R80.1 U24.1
$5N95: C112.1 R72.1 U24.7
$5N129: F1.1 J16.2
$5N162: R41.2 R100.2 R128.1
$5N171: R99.2 R103.2 R246.1
$6N20: C13.1 R101.2 U9.1
$6N32: L3.1 U9.6
$6N42: R187.2 R188.1
$6N44: R189.1 R253.2
$6N47: R31.1 R188.2 R189.2 R193.1
$6N77: C119.1 R82.2 U18.8
$6N85: L4.1 U18.3
$6N109: C14.1 R190.1 R192.2
$6N179: R190.2 R191.1
$6N194: R193.2 U9.2
$6N199: R194.1 U18.7
$7N68: L6.2 U26.6
$7N76: C120.1 R83.2 U26.4
$7N92: R11.1 R195.2 R198.1 R240.2
$7N111: C15.1 R199.1 R200.2
$7N113: R195.1 R199.2
$7N137: L5.2 U26.3
$7N148: C16.1 R201.2 R202.1
$7N150: R196.2 R201.1
$7N160: C121.1 R84.2 U26.2
$7N170: R198.2 U26.8
$7N173: R197.1 U26.1
$7N232: R12.1 R196.1 R197.2 R241.1
$8N21: L7.2 U27.3
$8N27: C17.1 R206.1 R207.2
$8N29: R205.1 R206.2
$8N42: C122.1 R85.2 U27.4
$8N46: L8.2 U27.6
$8N75: C123.1 R86.2 U27.2
$8N88: R203.1 U27.1
$8N94: R204.2 U27.8
$8N96: R14.1 R203.2 R245.2
$8N120: C118.1 U21.4
$8N176: R13.1 R204.1 R205.2 R242.2
$10N57: R113.2 U3.K1
$11N85: R114.2 U14.L8
$11N191: C153.1 R174.1 R175.2 U14.M8
$11N192: C156.1 R176.1 R177.2 U14.H1
$11N529: R115.2 U15.L8
$11N533: C161.1 R178.2 R179.1 U15.H1
$11N534: C159.1 R180.2 R181.1 U15.M8
$12N8: C218.1 R29.2 U3.P1 X1.1
$12N11: C219.1 R249.2 X1.3
$12N13: R29.1 R249.1 U3.P2
$12N96: C2.1 U3.M1 X2.1
$12N98: C3.1 U3.M2 X2.2
$12N110: U3.N3 U25.1
$12N181: R19.2 U3.A20
$12N307: R801.2 U3.R3
$12N323: R8.2 U3.B19
$12N325: R20.2 U3.A21
$12N327: R25.2 U3.B20
$12N329: R88.2 U3.B21
$12N331: R90.2 U3.C16
$12N369: R800.2 U3.C17
$12N378: R21.2 U3.D18
$13N13: R22.2 U3.AA4
$13N35: R700.2 U3.B22
$13N216: R23.2 U3.Y5
$13N220: R24.2 U3.W5
$13N249: R500.2 U3.AA3
$13N316: R44.2 SW1.5
$13N317: R46.2 SW1.6
$13N318: R45.2 SW1.7
$13N319: R42.2 SW1.8
$13N321: R47.2 SW2.8
$13N322: R48.2 SW2.7
$13N323: R49.2 SW2.6
$13N324: R50.2 SW2.5
$14N64: R33.2 R34.2 U3.G20
$14N204: C47.1 C228.1 U3.AB21
$14N216: R26.1 U3.R22
$14N221: R27.1 U3.N21
$14N244: C191.2 U3.Y22
$14N249: C192.2 U3.Y21
$14N260: C194.2 U3.V22
$14N261: C195.2 U3.V21
$14N269: R91.1 R98.2 U3.AA20
$14N610: R780.1 U3.N22
$14N612: R776.1 U3.R20
$14N614: R778.1 U3.T22
$14N639: R784.1 U3.R21
$14N641: R782.1 U3.P22
$14N649: R884.1 U3.N20
$14N651: R882.1 U3.L22
$14N653: R880.1 U3.M21
$14N655: R788.1 U3.L21
$14N668: R786.1 U3.M22
$14N704: R92.1 U3.P19
$14N709: R94.1 U3.L19
$15N123: R89.2 R136.1 U7.19
$15N332: R212.1 R213.1 U4.7
$16N153: L9.1 U2.48
$16N321: C66.1 T1.1 T1.4 T1.7 T1.10
$16N362: C216.1 R130.1
$16N389: J20.14 R4.2
$16N404: R252.1 U2.39
$16N414: R216.2 R217.2 U2.42
$16N425: C65.1 C239.1 LB11.2 OSC1.4(TP-4)
$16N440: OSC1.3(TP-3) R28.1
$16N442: R28.2 R217.1
$16N448: OSC1.1(TP-1) R149.1
$16N468: D17.1 R130.2 T1.15 T1.18 T1.21 T1.24
$16N490: R218.2 U2.38
$16N505: R1004.2 U2.19
$16N560: J20.16 R5.2
$17N641: R39.1 U22.69
$17N642: R214.1 U22.56
$17N661: R37.1 U22.54
$17N662: R35.1 U22.70
$17N663: R38.1 U22.55
$17N666: R150.1 R151.1 U22.72
$17N672: C4.1 R36.2 U22.51
$18N239: J28.13 R219.1
$18N447: D19.1 R6.2
$18N493: D20.1 R183.2 R184.2
$19N136: R112.1 U1.2
$20N434: C179.2 Q1.1 R9.1 R104.2
$20N436: Q3.1 R54.2
$20N437: Q3.3 R9.2
$20N553: C180.2 Q2.1 R10.1 R105.2
$20N554: Q4.1 R57.2
$20N555: Q4.3 R10.2
$21N200: R235.1 R251.2 U19.7
$21N201: C181.2 Q5.2 R1.1 R30.2 R32.1 R182.1 U19.1
$21N203: C221.1 LB13.1 R76.1
$21N204: R97.2 R108.1 R250.2 U19.3
$21N209: Q5.1 R1.2
$21N213: C220.1 LB14.1 R97.1
$21N216: R109.1 R110.2 U19.5
$21N217: R78.1 R79.1 R111.2
$21N220: R40.1 R110.1 R166.2
$21N227: R79.2 R251.1 U19.6
$21N229: C181.1 R30.1 R76.2 R235.2 U19.2
$21N230: C85.1 R2.2 R111.1
$21N306: C124.2 U20.12
$21N314: C87.1 U20.9
$21N315: R243.1 U20.1
$21N316: R244.1 U20.4
$22N94: C90.1 C263.1 C264.1 J1.84 J1.86 J1.88 J1.90 L12.1(TP-1)
$24N1066: D15.2 R171.1
$25N49: C250.1 R124.1 R125.2
$25N63: C250.2 R126.1 R127.2
$25N107: C25.1 R116.1 R117.2
$25N123: C26.1 R118.2 R119.2
$25N140: C249.1 R120.1 R121.2
$25N160: C249.2 R122.1 R123.2
$26N28: C125.2 R131.1
$26N31: C144.1 R16.1 R131.2 R237.1
$26N33: C11.1 R16.2 U5.2
$26N37: C11.2 R134.2 R236.2 R237.2 U5.3
$26N58: C7.2 U5.6
$26N69: C8.1 U5.7
$26N71: C8.2 U5.8
$26N114: C126.1 R132.2
$26N116: C143.1 R17.2 R132.1 R238.2
$26N122: C12.2 R17.1 U5.13
$26N127: C12.1 R133.1 R238.1 R239.2 U5.12
$26N154: R3.2 R15.2 R233.1
$26N162: R3.1 U5.11
$27N23: R172.2 U8.4
$27N24: R173.2 U8.5
$27N30: C139.2 R172.1
$27N32: C140.2 R173.1
$27N58: LB18.1 U8.1
$27N60: LB19.1 U8.8
$27N64: C210.1 J24.1 LB18.2
$27N67: C211.1 J24.2 LB19.2
$28N945: R889.1 U6.6
$28N947: R231.2 U6.3
$28N948: R230.2 U6.2
$28N1280: Q6.1 R185.2
$28N1296: C197.1 D16.2 K1.1 R77.2
$28N1297: D16.1 K1.8 Q6.3
$28N1347: R888.1 U6.7

Pads without a net: J1 16 24 26 30 32 36 38 42 44 48 50 54 56 58 60 64 66 68 70 72 80 82; J17 11 12; J18 1 2 3 4 5 6 8 10 13 23 24 26 28 30 32 33 34 35 36 37 38 39 40 41 42 43 44 45 46 48; J19 1 2 3 4 5 6 8 10 13 23 24 26 28 30 32 33 34 35 36 37 38 39 40 41 42 43 44 45 46 48; J28 14; J29 2 4; J30 2 4; K1 2 5 6 7; NOREF#12 1; NOREF#13 1; NOREF#27 1; NOREF#31 1; NOREF#32 1; NOREF#33 1; U2 12 20 33 43 46; U3 AA1 AA2 AA15 H19 H21 H22 J19 J20 J21 J22 R19 T19 T20 U19 U22 W3 W4 W17 W18 Y1 Y2 Y3; U7 1 2 3 4 5 6 10 11 14 15 20 21 22 23 24 25 26 27 28 33 34 35 38 39 40 45 46 47 48; U9 8; U10 5; U14 J1 J9 L1 L9; U15 J1 J9 L1 L9; U16 4 5 6 11 12 13 14; U18 1; U20 6; U22 24 25 27 28 29 30 31 32 36 37 38 39 40 41 44 45 50 52

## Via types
v1: diameter 0.406, hole 0.203, TOP to BOTTOM, 319 vias
v2: diameter 0.559, hole 0.254, TOP to BOTTOM, 1653 vias

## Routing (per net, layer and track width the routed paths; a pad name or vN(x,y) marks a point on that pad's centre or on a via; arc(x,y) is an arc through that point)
0.9V_VDD: length 8.6
  TOP w0.254: U3.N12 88.5,50.14 v1(88.5,50.14) U3.M12 ; v1(90.45,51.44) U3.K15 ; U3.P12 v1(88.5,48.84)
  BOTTOM w0.254: v1(88.5,48.84) 88.53,48.8 C261.1 ; LB7.2 88.22,50.14 v1(88.5,50.14) 88.9,50.54 C188.1
  BOTTOM w0.381: v2(101.76,24.65) 98.86,24.65 97.59,23.38 R242.1
  vias: v2(101.76,25.8) v2(102.77,25.8) v2(102.77,24.65)
0.9V_VDD_CPU: length 7.4
  TOP w0.381: R240.1 v2(114.31,53.46)
  BOTTOM w0.381: v2(114.31,53.46) 114.84,53.99 114.84,58.43 v2(113.95,59.32)
  vias: v1(89.8,52.74) v1(90.45,52.74) v1(91.1,52.74) v2(112.93,59.32) v2(112.93,58.31) v2(113.95,58.31)
0.9V_VDD_DDR: length 18.3
  TOP w0.254: U3.J8 86.22,52.41 v1(86.55,52.74) U3.H8 ; U3.H10 v1(87.85,52.74) U3.H11
  BOTTOM w0.254: v1(86.55,52.74) 86.59,52.69 C184.1 ; v1(87.85,52.74) 87.89,52.69 C185.1
  BOTTOM w0.381: v2(102.49,59.2) 101.76,58.46 101.76,48.66 102.27,48.15 R241.2
  vias: v2(102.49,58.18) v2(103.48,59.2) v2(103.48,58.18)
0.9V_VDD_MEDIA: length 9.8
  TOP w0.254: U3.R9 v1(87.2,48.19) ; U3.N15 v1(90.45,49.49) ; U3.R13 89.47,48.52 v1(89.8,48.84) U3.R14 ; U3.P8 86.01,48.95 86.01,48.73 U3.R8 v1(86.55,48.19) ; U3.R15 v1(90.45,48.84) U3.P15
  ART03 w0.381: v2(105.06,33.03) 106.58,33.03 v2(108.95,30.67)
  BOTTOM w0.381: v2(108.95,30.67) R186.1
  vias: v2(104.04,34.05) v2(104.04,33.03) v2(105.06,34.05)
1.2V_SII9022: length 4.7
  BOTTOM w0.305: 131.08,47.74 C76.1 ; C76.1 131.6,47.22 ; C76.1 132.12,47.74 ; C106.1 129.21,48.67 ; C106.1 129.74,48.15 ; C106.1 129.21,47.63 ; 136.81,47.22 C69.1 ; C69.1 136.29,47.74 ; C69.1 137.33,47.74
1.8V: length 63.4
  TOP w0.254: U3.V10 U3.V9 v1(86.55,46.24) ; U3.V6 v1(84.6,46.24) U3.V5 ; U3.M18 v1(93.05,50.79)
  TOP w0.381: R14.2 100.11,15.59 v2(100.79,16.27)
  ART03 w0.381: 88.3,47.39 88.93,48.02 90.68,48.02 91.11,48.45 91.11,49.67 92.23,50.79 v1(93.05,50.79)
  ART04 w0.508: v2(100.79,16.27) v2(99.7,16.27) 99.09,16.27 95.28,20.08 90.2,20.08 83.85,26.43 83.85,27.83 82.26,29.42 82.26,32.83 80.8,34.29 v1(80.8,44.21)
  BOTTOM w0.254: C150.1 84.35,46.49 v1(84.6,46.24) ; C177.1 86.89,45.9 v1(86.55,46.24) ; v1(93.05,50.79) C178.1
  BOTTOM w0.305: R43.2 79.66,43.41 ; R43.2 80.1,42.97 ; R43.2 79.21,42.97 ; R135.2 78.68,42.69 ; 78.16,44.22 R51.2 78.68,43.7
1V2A_SII9022A: length 4.7
  TOP w0.254: U22.66 v2(140.98,52.8) ; U22.60 v2(141,49.8)
  BOTTOM w0.305: 140.33,52.8 C67.1 139.88,52.22 ; C68.1 139.88,50.89 ; C68.1 140.33,50.31 ; C68.1 139.88,49.72
1V2D_SII9022A: length 9.1
  TOP w0.254: U22.47 v2(135.72,45.63) ; U22.12 v2(133.72,55.52) ; U22.53 v2(138.72,45.48) ; U22.42 v2(133.22,45.63) ; U22.5 v2(137.22,55.52) ; U22.26 v2(128.94,52.3)
  BOTTOM w0.305: 133.24,54.52 C74.1 ; C74.1 133.76,55.04 ; C74.1 134.28,54.52 ; C75.1 138.09,54.52 ; C75.1 137.57,55.04 ; C75.1 137.05,54.52
3V3: length 110.9
  TOP w0.203: U2.21 v2(119.36,72.37) ; U2.15 v2(119.46,74.77)
  TOP w0.254: U3.N4 83.62,49.81 v1(83.3,50.14) ; U20.15 v2(62.26,15.51) ; U7.37 85.6,27.16 v2(85.88,27.45) ; v2(64.42,18.43) 64.92,17.93 U20.10 ; v1(92.16,48.05) 92.35,47.86 U3.T18 ; U7.12 63.69,27.16 v2(63.53,27.32) ; U3.V15 v1(90.45,46.89)
  TOP w0.381: R136.2 v2(60.74,24.78) ; C53.1 v2(104.3,72.79) ; R147.1 R142.2 v2(123.73,65.8) ; v2(104.3,76.79) C246.1 C235.1 ; R140.2 v2(60.63,30.22) ; C87.2 v2(67.47,18.68) ; R218.1 v2(130.59,71.77) ; v2(105.57,13.98) 105.57,13.73 109.76,9.54 R128.2 ; C265.1 110.77,73.29 v2(110.77,73.29) ; v2(141.13,60.34) 140.72,60.75 R53.2 R52.2 ; v2(104.3,70.12) 104.63,69.79 C58.1 ; R83.1 R84.1 109.95,50.5 111.23,49.21 112.37,49.21 v2(112.43,49.27) ; R145.1 v2(113.29,72.99) ; R144.1 v2(114.84,73.55) ; C179.1 v2(135.79,27.19) ; v2(77.75,30.24) 77.73,30.27 U16.2 ; R149.2 v2(129.62,64.66) ; C266.1 v2(108.85,79.34) ; R148.1 v2(114.84,75.58) ; Q1.2 v2(138.97,27.7) ; LB11.1 v2(126.85,66.39) ; D19.2 v2(143.82,44.44) ; C40.1 v2(105.85,66.74) ; R104.1 v2(135.79,28.21) ; R158.1 v2(145.9,24.68) ; C24.1 v2(108.85,66.82) ; R146.1 v2(114.84,74.56)
  ART03 w0.381: v2(91.6,27.57) 91.47,27.45 91.47,22.37 v2(91.6,22.24)
  POWER5 w0.381: 78.14,8.65 J21.1 ; J21.1 77.44,9.54 ; J21.1 78.14,10.43 ; 93.31,9.29 J25.1 94.01,10.18 ; 79.39,10.43 J21.2 79.39,8.65
  BOTTOM w0.254: LB8.2 85.41,49.84 v1(84.99,49.42) 85.56,48.85 C189.1 ; C39.1 84.49,52.81 LB6.1 85.36,52.81 v1(85.81,53.25) ; U10.27 v2(108.85,79.34) ; C44.1 83.15,50.28 v1(83.3,50.14) ; LB100.2 93.69,52.73 v1(93.05,52.09) 93.01,52.05 C152.1 ; U10.10 v2(104.3,72.79) ; U10.18 v2(104.3,76.79) ; LB9.1 92.6,47.61 v1(92.16,48.05) 92.47,48.37 C49.1 ; U10.56 v2(105.85,66.74) ; U10.38 v2(110.77,73.29) ; v2(72.42,33.07) 72.19,32.84 R139.2 ; LB10.2 90.51,46.95 v1(90.45,46.89) 90.44,46.88 C151.1 ; U10.50 v2(108.85,66.82) ; U10.4 104.63,69.79 v2(104.3,70.12) ; C187.1 92.21,54.32 v1(92.49,54.6) 92.88,54.99 C149.1
  BOTTOM w0.305: C88.1 62.79,24.12 ; C88.1 62.79,23.08 ; C88.1 63.31,23.6 ; 119.5,72.4 C59.1 ; C59.1 120.02,72.93 ; C59.1 120.02,71.88 ; C37.1 111.56,50.07 ; C37.1 111.56,49.02 ; C37.1 112.08,49.54 ; C55.1 120.4,76.23 ; C55.1 120.4,75.19 ; C55.1 119.88,75.71 ; 129.23,61.61 C77.1 ; C77.1 129.75,62.13 ; C77.1 129.75,61.09 ; v1(84.6,48.19) 84.6,48.5 C175.1
  BOTTOM w0.381: C50.1 85.86,27.47 v2(85.88,27.45) 85.91,27.47 C51.1 ; R87.2 v2(92.2,60.31) ; C229.1 63.72,27.51 v2(63.53,27.32) ; R5.1 141.91,61.2 142.27,60.85 v2(142.27,60.34) ; v2(89.32,73.56) R65.1 R64.1 ; R82.1 107.62,27.07 v2(107.83,27.27) ; R166.1 v2(84.87,83.33) ; R63.1 v2(95.06,73.56) ; R101.1 61.19,75.02 v2(62.51,76.34) ; v2(91.6,22.24) 91.7,22.14 R86.1 R85.1 ; R66.1 v2(90.57,73.56) ; R62.1 v2(96.31,73.56) ; Q2.2 v2(139.98,33.42) ; R250.1 v2(71.4,81.29) ; R159.1 v2(145.9,37.78) ; R61.1 v2(97.56,73.56) ; R67.1 v2(91.82,73.56) ; R60.1 v2(98.81,73.56) ; R105.1 v2(135.67,33.16) ; C180.1 v2(135.67,31.38)
  vias: v2(62.51,77.36) v2(63.66,77.36) v2(63.66,76.34) v2(64.42,20.21) v2(64.42,19.32) v2(65.05,60.72) v2(65.05,59.7) v2(66.07,60.72) v2(66.07,59.7) v2(75.85,10.68) v2(78.52,29.73) v2(92.61,27.57) v2(93.15,11.93) v2(94.32,33.92) v2(95.33,33.92) v2(96.8,29.61) v2(96.8,28.59) v2(104.55,15.13) v2(104.55,13.98) v2(105.57,15.13) v2(111.92,46.17) v2(112.93,46.17) v2(123.7,56.91) v2(123.7,55.9) v2(124.72,56.91) v2(124.72,55.9) v2(129.57,39.13) v2(130.26,38.42)
3V3_C: length 20.6
  TOP w0.381: R77.1 v2(33.18,71.39) ; U6.8 v2(37.24,72.4) ; D15.1 v2(7.02,47.51)
  ART04 w0.381: v2(7.02,47.51) 12.4,47.51 16.97,42.94 v2(19.84,42.94)
  BOTTOM w0.381: R69.1 v2(21.62,46.01) ; C100.1 v2(37.24,72.4)
  vias: v2(19.84,41.92) v2(20.99,42.94) v2(20.99,41.92) v2(43.08,38.62) v2(43.08,37.86) v2(43.08,37.1) v2(43.08,36.34)
5V0: length 19.6
  TOP w0.254: J28.18 152.37,46.18 v2(151.29,45.1)
  ART04 w0.381: v2(129.44,33.67) 129.44,30.22 v2(125.51,26.28)
  BOTTOM w0.305: 149.75,49.01 C109.1 ; C109.1 150.79,49.01 ; C109.1 150.27,48.49 ; 118.62,51.44 C92.1 118.1,51.96 ; 118.62,53.5 C89.1 118.1,52.97
  BOTTOM w0.381: v2(140.42,44.01) 140.39,43.98 C80.1 D20.2 ; v2(125.51,26.28) R246.2
  vias: v2(115.85,52.06) v2(115.85,51.07) v2(116.85,52.06) v2(116.85,51.04) v2(130.46,33.67) v2(131.48,33.67) v2(132.49,33.67) v2(150.4,45.1)
5V0_C:
  vias: v2(25.86,50.69) v2(25.86,48.91) v2(27.28,36.87) v2(27.28,35.85) v2(28.3,36.87) v2(28.3,35.85) v2(47,41.65) v2(47.02,42.6)
5V_AUDIO: length 2.1
  TOP w0.305: 23.37,58.96 C182.1 22.85,58.43 ; 22.85,57.42 C183.1 23.37,56.9
5V_USB2.0:
  vias: v2(14,48.53) v2(14,47.26) v2(15.27,48.53) v2(15.27,47.26)
12V0: length 11
  BOTTOM w0.356: R75.1 129.06,23.38 129.7,22.75 v2(129.7,20.97) ; v2(113.31,19.06) 113.19,19.06 111.66,17.54 111.66,15.28 R74.1
AGND: length 275.5
  TOP w0.305: 28.19,13.35 D7.2 ; D7.2 28.66,13.86 ; D7.2 28.66,12.84 ; 28.5,13.97 C258.2 ; C258.2 27.98,14.49 ; C258.2 28.5,15.01 ; 21.99,14.18 C98.2 ; C98.2 23.03,14.18 ; C98.2 22.51,13.65 ; R171.2 12.52,46.24 ; R171.2 11.99,46.76 ; R171.2 11.99,45.72 ; 12.72,33.43 C215.2 ; C215.2 13.24,33.95 ; C215.2 13.76,33.43 ; 16.29,28.29 R236.1 ; R236.1 15.77,28.81 ; R236.1 16.81,28.81 ; 12.86,18.5 D6.2 ; D6.2 13.87,18.5 ; D6.2 13.37,18.97 ; C252.2 31.25,16.16 ; C252.2 31.25,15.11 ; C252.2 31.77,15.64 ; R239.1 16.81,33.43 ; R239.1 16.29,33.95 ; R239.1 15.77,33.43 ; 12.9,36.09 J14.8 ; J14.8 14.24,37.43 ; J14.8 11.57,37.43 ; J14.8 12.9,38.76 ; D12.2 12.6,33.27 ; D12.2 11.59,33.27 ; D12.2 12.1,33.74 ; D14.1 16.03,81.37 ; D14.1 15.52,81.84 ; D14.1 15.02,81.37 ; C96.2 21.89,14.18 ; C96.2 20.85,14.18 ; C96.2 21.37,13.65 ; 12.1,28.5 D11.2 ; D11.2 12.6,28.97 ; D11.2 11.59,28.97 ; J10.1 29.56,82.69 ; J10.1 27.14,82.69 ; J10.1 28.35,83.9 ; J10.1 28.35,81.48 ; 44.42,23 J11.1 ; J11.1 46.83,23 ; J11.1 45.62,24.21 ; J11.1 45.62,21.79 ; D4.2 8.47,36.08 ; D4.2 8,35.57 ; D4.2 8.47,35.07 ; 12.98,15.82 D5.2 ; D5.2 14,15.82 ; D5.2 13.49,15.35 ; 32.67,20.58 C95.2 ; C95.2 32.67,21.62 ; C95.2 32.15,21.1 ; C253.2 39.55,17.55 ; C253.2 39.55,16.51 ; C253.2 40.07,17.03 ; 3.9,54.62 J15.2 ; J15.2 6.57,54.62 ; J15.2 5.24,56.47 ; J15.2 5.24,52.78 ; 36.84,17.65 C259.2 ; C259.2 36.31,18.18 ; C259.2 36.84,18.7 ; 23.92,39.5 R107.1 23.4,40.02 ; 17.16,20.14 C25.2 ; C25.2 18.2,20.14 ; C25.2 17.68,20.66 ; 23.65,24.78 R106.1 ; R106.1 24.17,24.26 ; R106.1 24.17,25.3 ; 15.52,78.59 D13.2 ; D13.2 16.03,79.06 ; D13.2 15.02,79.06 ; 5.9,41.53 J14.5 ; J14.5 7.24,42.87 ; J14.5 4.57,42.87 ; J14.5 5.9,44.2 ; C260.2 39.55,18.7 ; C260.2 40.07,18.18 ; C260.2 39.55,17.65 ; R234.2 23.79,49.44 ; R234.2 22.75,49.44 ; R234.2 23.27,49.96 ; 12.72,28.81 C214.2 ; C214.2 13.24,28.29 ; C214.2 13.76,28.81 ; 45.88,40.31 C94.2 ; C94.2 45.43,40.76 ; C94.2 46.32,40.76 ; 21.61,25.91 C7.1 ; C7.1 22.09,26.43 ; C7.1 21.61,26.95 ; C257.2 31.25,15.01 ; C257.2 31.25,13.97 ; C257.2 31.77,14.49 ; 36.84,17.55 C254.2 36.84,16.51 ; 11.68,40.15 J14.4 ; J14.4 13.59,40.15 ; J14.4 12.63,38.94 ; J14.4 12.63,41.35 ; 5.9,36.09 J14.7 ; J14.7 4.57,37.43 ; J14.7 7.24,37.43 ; J14.7 5.9,38.76 ; 10.77,35.07 D3.2 ; D3.2 10.77,36.08 ; D3.2 11.24,35.57 ; 17.04,15.8 C26.2 18.08,15.8 ; C143.2 19.46,39.98 ; C143.2 18.94,39.46 ; C143.2 19.98,39.46 ; J14.6 14.24,42.87 ; J14.6 11.57,42.87 ; J14.6 12.9,44.2 ; J14.6 12.9,41.53 ; R152.2 24.64,45.75 ; R152.2 24.12,45.23 ; R152.2 24.64,44.71 ; C251.2 28.5,16.16 ; C251.2 27.98,15.64 ; C251.2 28.5,15.11 ; 19.59,24.73 C144.2 20.11,24.21 ; C182.2 24.71,58.43 ; 37.04,13.86 D10.2 37.04,14.87 ; C97.2 21.87,20.66 ; C97.2 21.35,20.14 ; C97.2 22.4,20.14 ; 32.95,64.01 R59.2 ; R59.2 32.43,64.53 ; R59.2 32.95,65.05 ; 39.47,13.86 D9.2 39.47,14.87 ; 31.09,12.84 D8.2 ; D8.2 31.09,13.86 ; D8.2 31.56,13.35 ; 24.19,56.9 C183.2 24.71,57.42 ; 43.85,34.9 C93.2 ; C93.2 43.32,35.42 ; C93.2 44.37,35.42 ; D2.2 13.62,55.28 ; C99.2 23.28,37.51
  TOP w0.356: v2(17.18,26.81) 17.51,27.15 U5.1 ; v2(17.51,35.45) U5.14
  TOP w0.381: C140.1 v2(26.83,64.66) ; v2(3.08,14.37) 3.08,12.59 v2(4.48,12.59) ; 12.33,55.28 D2.2 v2(13.11,56.02) ; U5.10 v2(20.11,32.8) ; C210.2 v2(17.43,59.45) ; C138.2 v2(14.76,14.1) ; v2(20.33,35.98) 20.6,36.26 R15.1 ; v2(4.48,19.7) 3.08,19.7 v2(3.08,17.92) ; D9.2 v2(40.29,14.37) ; C197.2 v2(31.65,71.39) ; R127.1 v2(41.05,19.45) ; D10.2 v2(36.23,14.37) ; U6.5 v2(41.05,72.15) ; v2(4.48,31.38) 3.08,31.38 v2(3.08,29.61) ; C211.2 v2(17.43,65.55) ; Q6.2 v2(34.32,69.1) ; v2(4.35,24.27) 3.08,24.27 v2(3.08,26.05) ; C137.2 v2(14.76,20.21)
  GND02 w0.305: J15.2 6.57,54.62 ; J15.2 5.24,56.47 ; J15.2 3.9,54.62 ; J15.2 5.24,52.78 ; J14.8 12.9,38.76 ; J14.8 11.57,37.43 ; J14.8 14.24,37.43 ; J14.8 12.9,36.09 ; 45.62,21.79 J11.1 ; J11.1 45.62,24.21 ; J11.1 46.83,23 ; J11.1 44.42,23 ; J14.6 14.24,42.87 ; J14.6 12.9,41.53 ; J14.6 11.57,42.87 ; J14.6 12.9,44.2 ; J10.1 28.35,83.9 ; J10.1 28.35,81.48 ; J10.1 27.14,82.69 ; J10.1 29.56,82.69 ; 4.57,42.87 J14.5 ; J14.5 5.9,41.53 ; J14.5 5.9,44.2 ; J14.5 7.24,42.87 ; 12.63,38.94 J14.4 ; J14.4 11.68,40.15 ; J14.4 12.63,41.35 ; J14.4 13.59,40.15 ; 5.9,36.09 J14.7 ; J14.7 4.57,37.43 ; J14.7 5.9,38.76 ; J14.7 7.24,37.43
  BOTTOM w0.305: 5.24,52.78 J15.2 ; J15.2 6.57,54.62 ; J15.2 3.9,54.62 ; J15.2 5.24,56.47 ; J11.1 46.83,23 ; J11.1 45.62,24.21 ; J11.1 44.42,23 ; J11.1 45.62,21.79 ; 28.35,81.48 J10.1 ; J10.1 28.35,83.9 ; J10.1 29.56,82.69 ; J10.1 27.14,82.69 ; R58.2 19.28,28.62 ; R58.2 20.62,28.62 ; R58.2 20.1,29.28 ; J14.5 7.24,42.87 ; J14.5 5.9,44.2 ; J14.5 4.57,42.87 ; J14.5 5.9,41.53 ; 11.57,37.43 J14.8 ; J14.8 14.24,37.43 ; J14.8 12.9,36.09 ; J14.8 12.9,38.76 ; J14.7 7.24,37.43 ; J14.7 5.9,38.76 ; J14.7 4.57,37.43 ; J14.7 5.9,36.09 ; R169.1 22.66,65.19 ; R169.1 23.99,65.19 ; R169.1 23.47,65.85 ; C100.2 37.24,74.87 ; C100.2 36.43,74.21 ; C100.2 37.76,74.21 ; 12.63,38.94 J14.4 ; J14.4 12.63,41.35 ; J14.4 13.59,40.15 ; J14.4 11.68,40.15 ; R112.2 22.89,49.09 ; R112.2 23.41,48.43 ; R112.2 22.08,48.43 ; J14.6 14.24,42.87 ; J14.6 11.57,42.87 ; J14.6 12.9,44.2 ; J14.6 12.9,41.53
  BOTTOM w0.508: 43.74,59.4 J19.72 40.9,59.4 ; 40.9,50.6 J19.50 43.74,50.6 ; 43.74,57.8 J19.68 40.9,57.8 ; 43.06,35.4 J19.12 40.9,35.4 ; 44.7,54.6 J19.59 v2(46.86,54.6) 47.54,54.6 ; 44.7,57.8 J19.67 v2(46.86,57.8) ; 40.9,39.4 J19.22 43.06,39.4 ; 44.7,43.4 J19.31 46.86,43.4 ; 44.7,49.8 J19.47 47.54,49.8 ; 47.54,51.4 J19.51 44.7,51.4 ; v2(40.8,53.23) 41.03,53 J19.56 43.74,53 ; 44.7,39.4 J19.21 46.86,39.4 ; 43.74,56.2 J19.64 41.35,56.2 41.28,56.12 40.9,56.12 ; 44.7,37 J19.15 46.86,37 ; 44.7,56.2 J19.63 v2(46.86,56.2) ; 46.86,41 J19.25 44.7,41 ; 46.87,33.34 46.41,33.8 J19.7 44.7,33.8 ; v2(46.86,61) J19.75 44.7,61 ; v2(46.86,59.4) J19.71 44.7,59.4 ; 47.54,53 J19.55 44.7,53
  vias: v2(1.05,81.42) v2(1.05,76.34) v2(1.05,71.26) v2(1.05,66.18) v2(1.05,61.1) v2(1.05,57.29) v2(1.05,51.96) v2(1.05,48.27) v2(1.05,44.46) v2(1.05,35.83) v2(1.05,30.75) v2(1.05,25.67) v2(1.05,20.59) v2(1.05,15.51) v2(1.05,10.43) v2(1.28,85) v2(1.94,8.4) v2(2.82,68.85) v2(3.46,81.29) v2(3.46,77.48) v2(3.46,73.67) v2(3.97,62.47) v2(4.25,8.9) v2(4.45,86.15) v2(5.36,84.22) v2(6.25,65.55) v2(6.25,10.94) v2(6.38,7.89) v2(6.63,16.27) v2(7.22,28.13) v2(7.9,62.5) v2(7.9,22.49) v2(8.03,18.18) v2(8.29,86.12) v2(8.29,34.81) v2(8.79,58.82) v2(8.79,8.78) v2(9.17,51.37) v2(9.3,33.29) v2(10.95,65.42) v2(10.95,34.81) v2(11.21,21.99) v2(11.33,33.27) v2(11.35,28.97) v2(11.46,31.89) v2(11.46,30.49) v2(11.71,8.9) v2(11.94,17.41) v2(12.1,61.86) v2(12.2,84.5) v2(12.35,57.93) v2(12.4,12.49) v2(12.48,26.43) v2(12.76,45.84) v2(13.24,65.42) v2(13.37,19.32) v2(13.49,15) v2(13.62,82.44) v2(13.75,10.43) v2(14,33.43) v2(14,28.81) v2(14.13,34.81) v2(14.25,23.26) v2(14.38,7.89) v2(14.58,84.95) v2(14.71,81.37) v2(14.64,75.83) v2(14.76,69.99) v2(15.12,83.57) v2(15.14,28.84) v2(15.27,54.75) v2(15.27,31.89) v2(15.27,30.49) v2(15.4,52.34) v2(15.4,50.81) v2(15.52,78.37) v2(15.52,33.43) v2(15.52,26.18) v2(16.29,27.95) v2(16.41,56.15) v2(16.67,86.2) v2(16.62,34.71) v2(17.15,50.33) v2(17.43,83.83) v2(17.56,58.18) v2(17.56,56.91) v2(17.68,20.95) v2(18.32,18.43) v2(18.32,15.94) v2(18.45,17.16) v2(18.95,52.47) v2(18.95,50.81) v2(19.08,31.89) v2(19.08,30.49) v2(19.46,40.4) v2(19.46,29.55) v2(19.59,24.99) v2(19.84,78.5) v2(19.84,7.89) v2(20.48,29.61) v2(20.99,52.97) v2(20.99,51.58) v2(21.11,49.67) v2(21.37,13.35) v2(21.75,86.2) v2(21.87,20.95) v2(22,18.56) v2(22,10.43) v2(22.13,15.89) v2(22.38,26.43) v2(22.51,13.35) v2(22.64,51.55) v2(22.76,78.5) v2(22.82,65.93) v2(23.27,50.31) v2(23.27,17.16) v2(23.4,40.27) v2(23.4,29.07) v2(23.4,24.78) v2(23.45,37.51) v2(23.78,66.05) v2(23.78,51.55) v2(23.78,20.72) v2(23.78,12.59) v2(23.91,45.48) v2(24.29,18.81) v2(24.36,50.64) v2(24.36,48.86) v2(24.54,47.39) v2(24.54,46.5) v2(24.67,79.77) v2(24.79,85.56) v2(24.8,13.6) v2(24.97,58.41) v2(24.97,57.29) v2(24.92,7.89) v2(25.24,82.52) v2(25.3,59.45) v2(25.3,10.3) v2(25.38,15.86) v2(25.81,78.5) v2(25.81,38.88) v2(25.94,40.91) v2(25.94,18.18) v2(26.32,29.1) v2(26.45,42.43) v2(26.83,86.2) v2(26.95,57.93) v2(26.95,55.77) v2(27.34,52.97) v2(27.34,39.13) v2(27.34,37.86) v2(27.46,79.77) v2(27.44,77.38) v2(27.46,49.42) v2(27.46,46.24) v2(27.72,15.64) v2(27.72,14.49) v2(27.72,13.35) v2(27.97,26.68) v2(27.97,21.73) v2(27.97,19.45) v2(28.35,42.43) v2(28.48,50.18) v2(28.48,45.61) v2(28.48,20.59) v2(28.61,78.5) v2(28.61,67.83) v2(28.91,29.12) v2(29.04,85.41) v2(29.24,60.47) v2(29.22,34.71) v2(29.27,33.34) v2(29.37,41.42) v2(29.49,56.02) v2(29.49,50.94) v2(29.49,46.88) v2(29.62,25.41) v2(29.75,28.21) v2(30,23.76) v2(29.93,19.45) v2(30,7.89) v2(30.26,79.77) v2(30.38,22.62) v2(30.51,58.69) v2(30.51,53.23) v2(30.51,48.78) v2(30.51,43.45) v2(30.51,36.84) v2(30.51,34.71) v2(30.51,33.29) v2(30.89,27.7) v2(31.1,84.24) v2(31.02,56.4) v2(31.15,19.45) v2(31.37,81.42) v2(31.4,78.5) v2(31.53,77.4) v2(31.53,51.07) v2(31.53,46.24) v2(31.53,40.91) v2(31.53,36.21) v2(31.53,30.75) v2(31.65,61.23) v2(31.78,20.72) v2(31.91,86.2) v2(31.91,22.62) v2(32.03,64.53) v2(32.03,15.64) v2(32.03,14.49) v2(32.03,13.35) v2(32.54,53.1) v2(32.54,48.53) v2(32.54,43.45) v2(32.54,38.62) v2(32.54,33.29) v2(32.54,28.21) v2(32.54,26.43) v2(32.8,79.77) v2(32.82,21.99) v2(32.92,25.16) v2(33.3,83.07) v2(33.3,61.23) v2(33.3,58.56) v2(33.43,57.04) v2(33.56,62.88) v2(33.56,51.07) v2(33.56,45.99) v2(33.56,40.91) v2(33.56,36.21) v2(33.56,30.75) v2(33.81,17.41) v2(33.91,81.35) v2(34.07,23.26) v2(34.07,9.79) v2(34.32,75.3) v2(34.32,13.35) v2(34.45,78.37) v2(34.57,54.5) v2(34.57,48.53) v2(34.57,43.45) v2(34.57,38.62) v2(34.57,33.29) v2(34.57,28.21) v2(34.57,25.29) v2(34.7,85.1) v2(34.83,79.77) v2(34.96,60.47) v2(34.96,56.78) v2(34.96,22.62) v2(35.08,7.89) v2(35.46,74.18) v2(35.59,45.99) v2(35.59,40.27) v2(35.59,36.21) v2(35.59,34.69) v2(35.59,30.75) v2(35.59,27.95) v2(35.72,21.86) v2(35.84,18.43) v2(36.1,51.07) v2(36.1,25.29) v2(36.1,17.54) v2(36.35,82.82) v2(36.48,58.31) v2(36.53,60.16) v2(36.61,48.53) v2(36.61,44.21) v2(36.61,37.73) v2(36.61,33.29) v2(36.61,28.21) v2(37.24,75.2) v2(37.62,51.07) v2(37.62,45.99) v2(37.62,40.91) v2(37.62,36.21) v2(37.62,30.75) v2(37.62,25.41) v2(37.75,8.78) v2(38.13,85.1) v2(38.13,79.21) v2(38.13,21.86) v2(38.38,24.53) v2(38.64,51.58) v2(38.64,48.53) v2(38.64,43.45) v2(38.64,39.77) v2(38.64,33.29) v2(38.64,28.21) v2(39.02,77.48) v2(39.02,62.37) v2(39.65,51.07) v2(39.65,47.26) v2(39.65,40.91) v2(39.65,36.08) v2(39.65,30.75) v2(39.65,25.67) v2(39.91,61.23) v2(40.21,18.18) v2(40.24,16.91) v2(40.8,50.56) v2(40.8,48.53) v2(40.8,46.12) v2(40.8,42.05) v2(40.8,39.38) v2(40.8,38.37) v2(40.8,37.35) v2(40.8,33.29) v2(40.8,28.21) v2(40.82,34.74) v2(40.92,24.78) v2(40.92,8.78) v2(41.05,86.2) v2(41.53,76.55) v2(41.94,13.22) v2(42.7,21.99) v2(43.08,61.1) v2(43.08,59.45) v2(43.08,58.18) v2(43.08,56.66) v2(43.08,52.97) v2(43.08,35.32) v2(43.08,31.38) v2(43.21,50.56) v2(43.21,27.83) v2(43.34,62.63) v2(43.46,24.91) v2(43.46,16.02) v2(43.97,76.85) v2(43.97,48.02) v2(44.1,54.5) v2(44.1,52.97) v2(44.1,45.48) v2(44.1,43.45) v2(44.1,42.18) v2(44.23,19.57) v2(44.35,73.93) v2(44.48,66.49) v2(44.48,40.91) v2(44.61,35.32) v2(44.61,33.42) v2(44.61,31.38) v2(44.99,29.73) v2(45.24,20.84) v2(45.62,27.57) v2(45.88,79.64) v2(46,83.83) v2(46.13,86.2) v2(46.39,71.01) v2(46.64,76.6) v2(46.77,24.91) v2(46.89,40.78) v2(47.07,65.8) v2(47.02,52.97) v2(47.15,62.63) v2(47.27,50.05) v2(47.27,47.64) v2(47.4,17.03) v2(48.04,84.6) v2(48.29,54.75) v2(48.29,39.38) v2(48.29,38.24) v2(48.29,32.15) v2(48.29,28.34) v2(48.29,24.53) v2(48.29,20.72) v2(48.29,13.1) v2(48.42,81.93) v2(48.42,74.06) v2(48.42,68.98) v2(48.42,63.9) v2(48.42,58.82) v2(48.42,45.99) v2(48.42,40.91) v2(48.42,35.83)
